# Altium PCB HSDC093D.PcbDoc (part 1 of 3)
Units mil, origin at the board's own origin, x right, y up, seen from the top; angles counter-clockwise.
Board outline 4360 x 2202.42 mil, 6 copper layers (Top Layer, GND1, VCC1, VCC2, GND2, Bottom Layer), stack 84.434 mil thick; 280 components, 182 nets, 800 pads, 401 vias.
Unrouted connection lines stored in the file: 5.
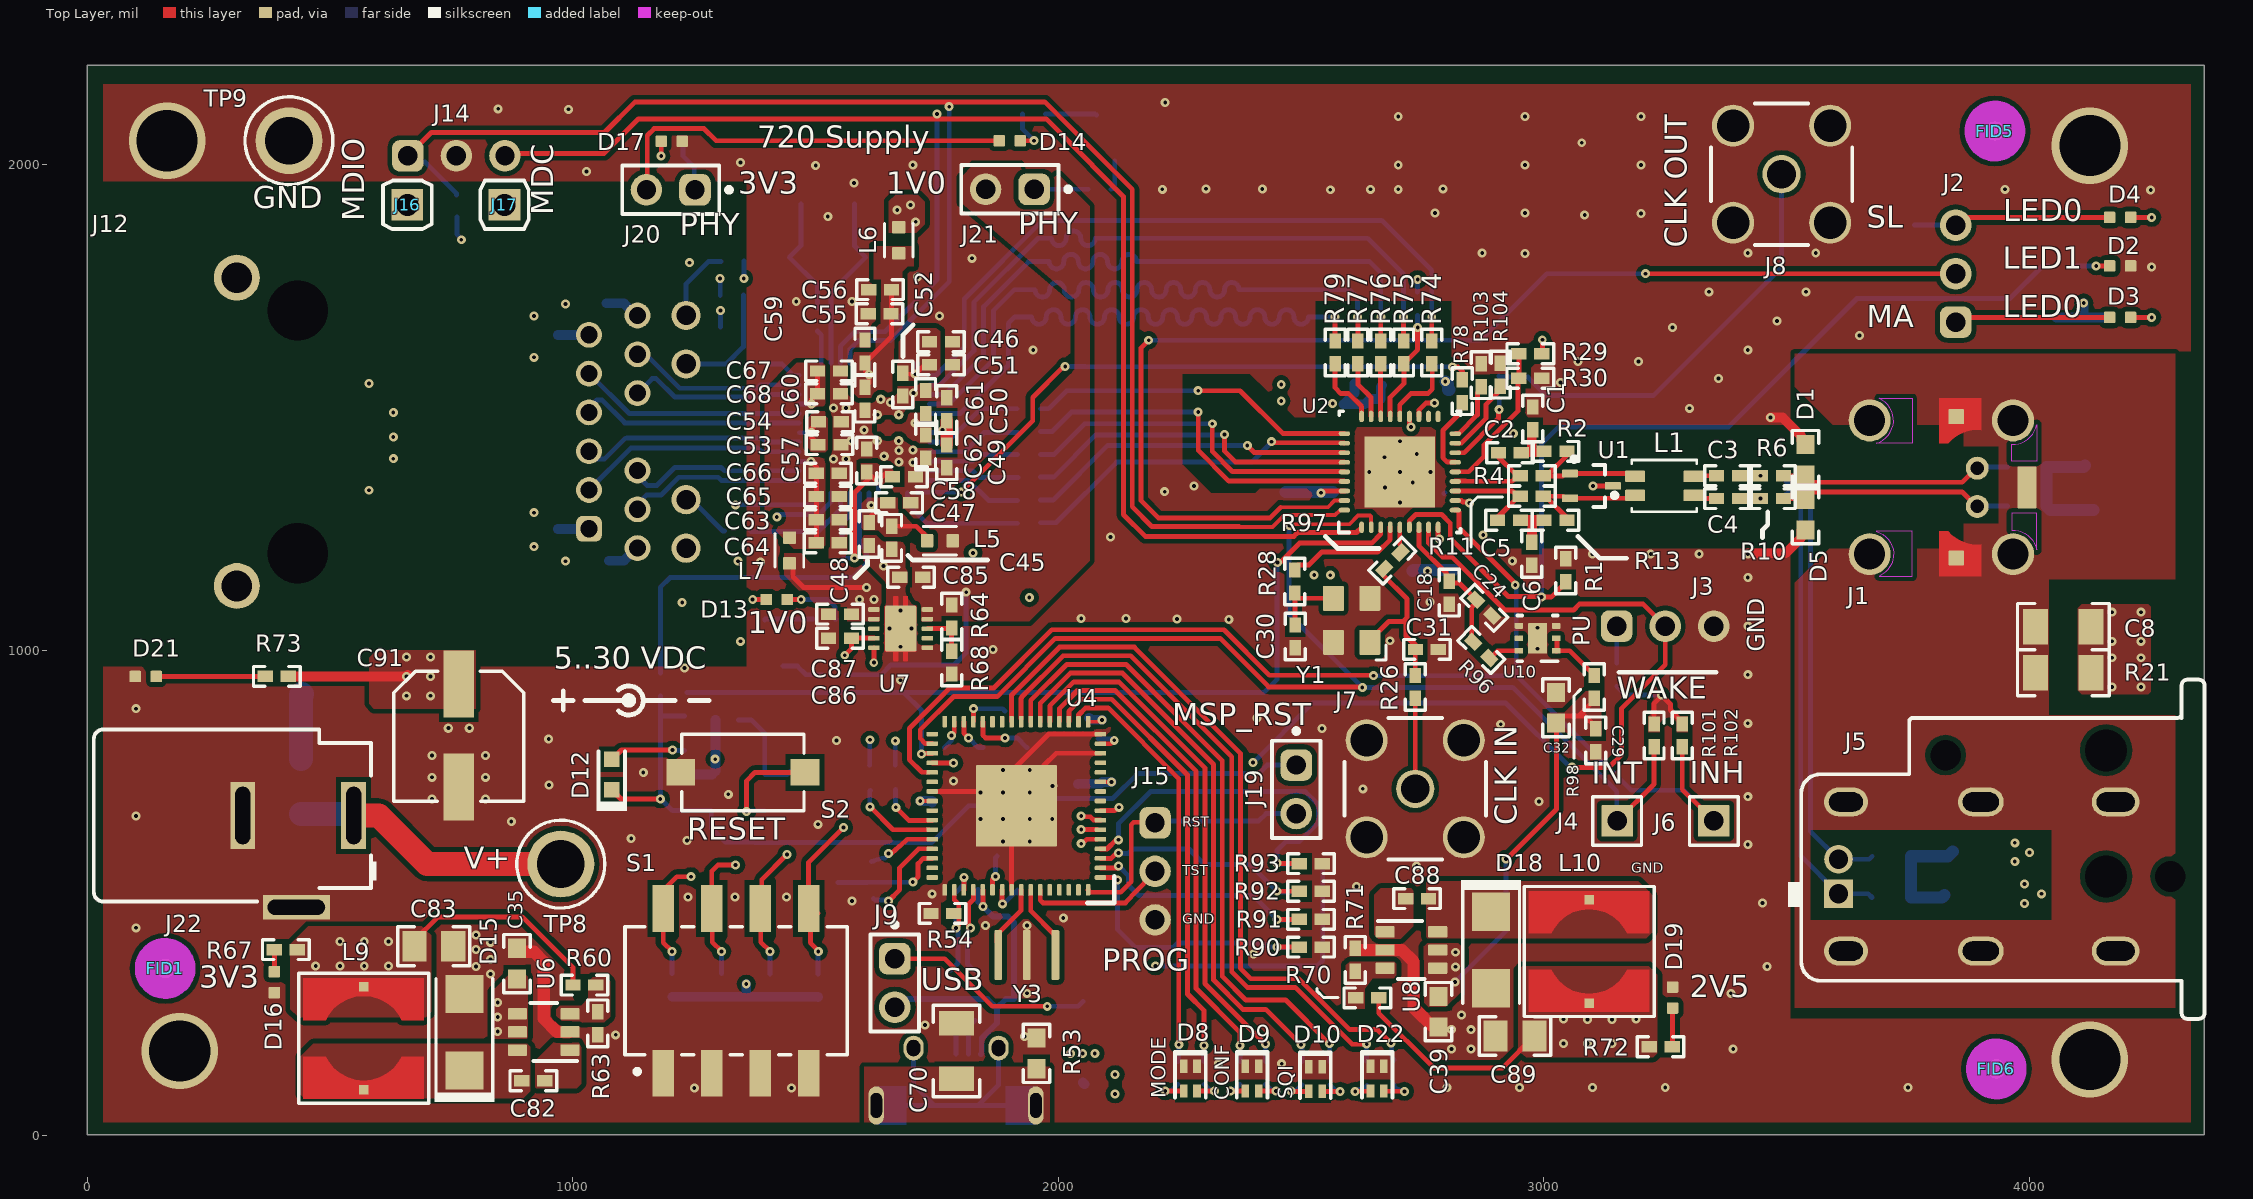
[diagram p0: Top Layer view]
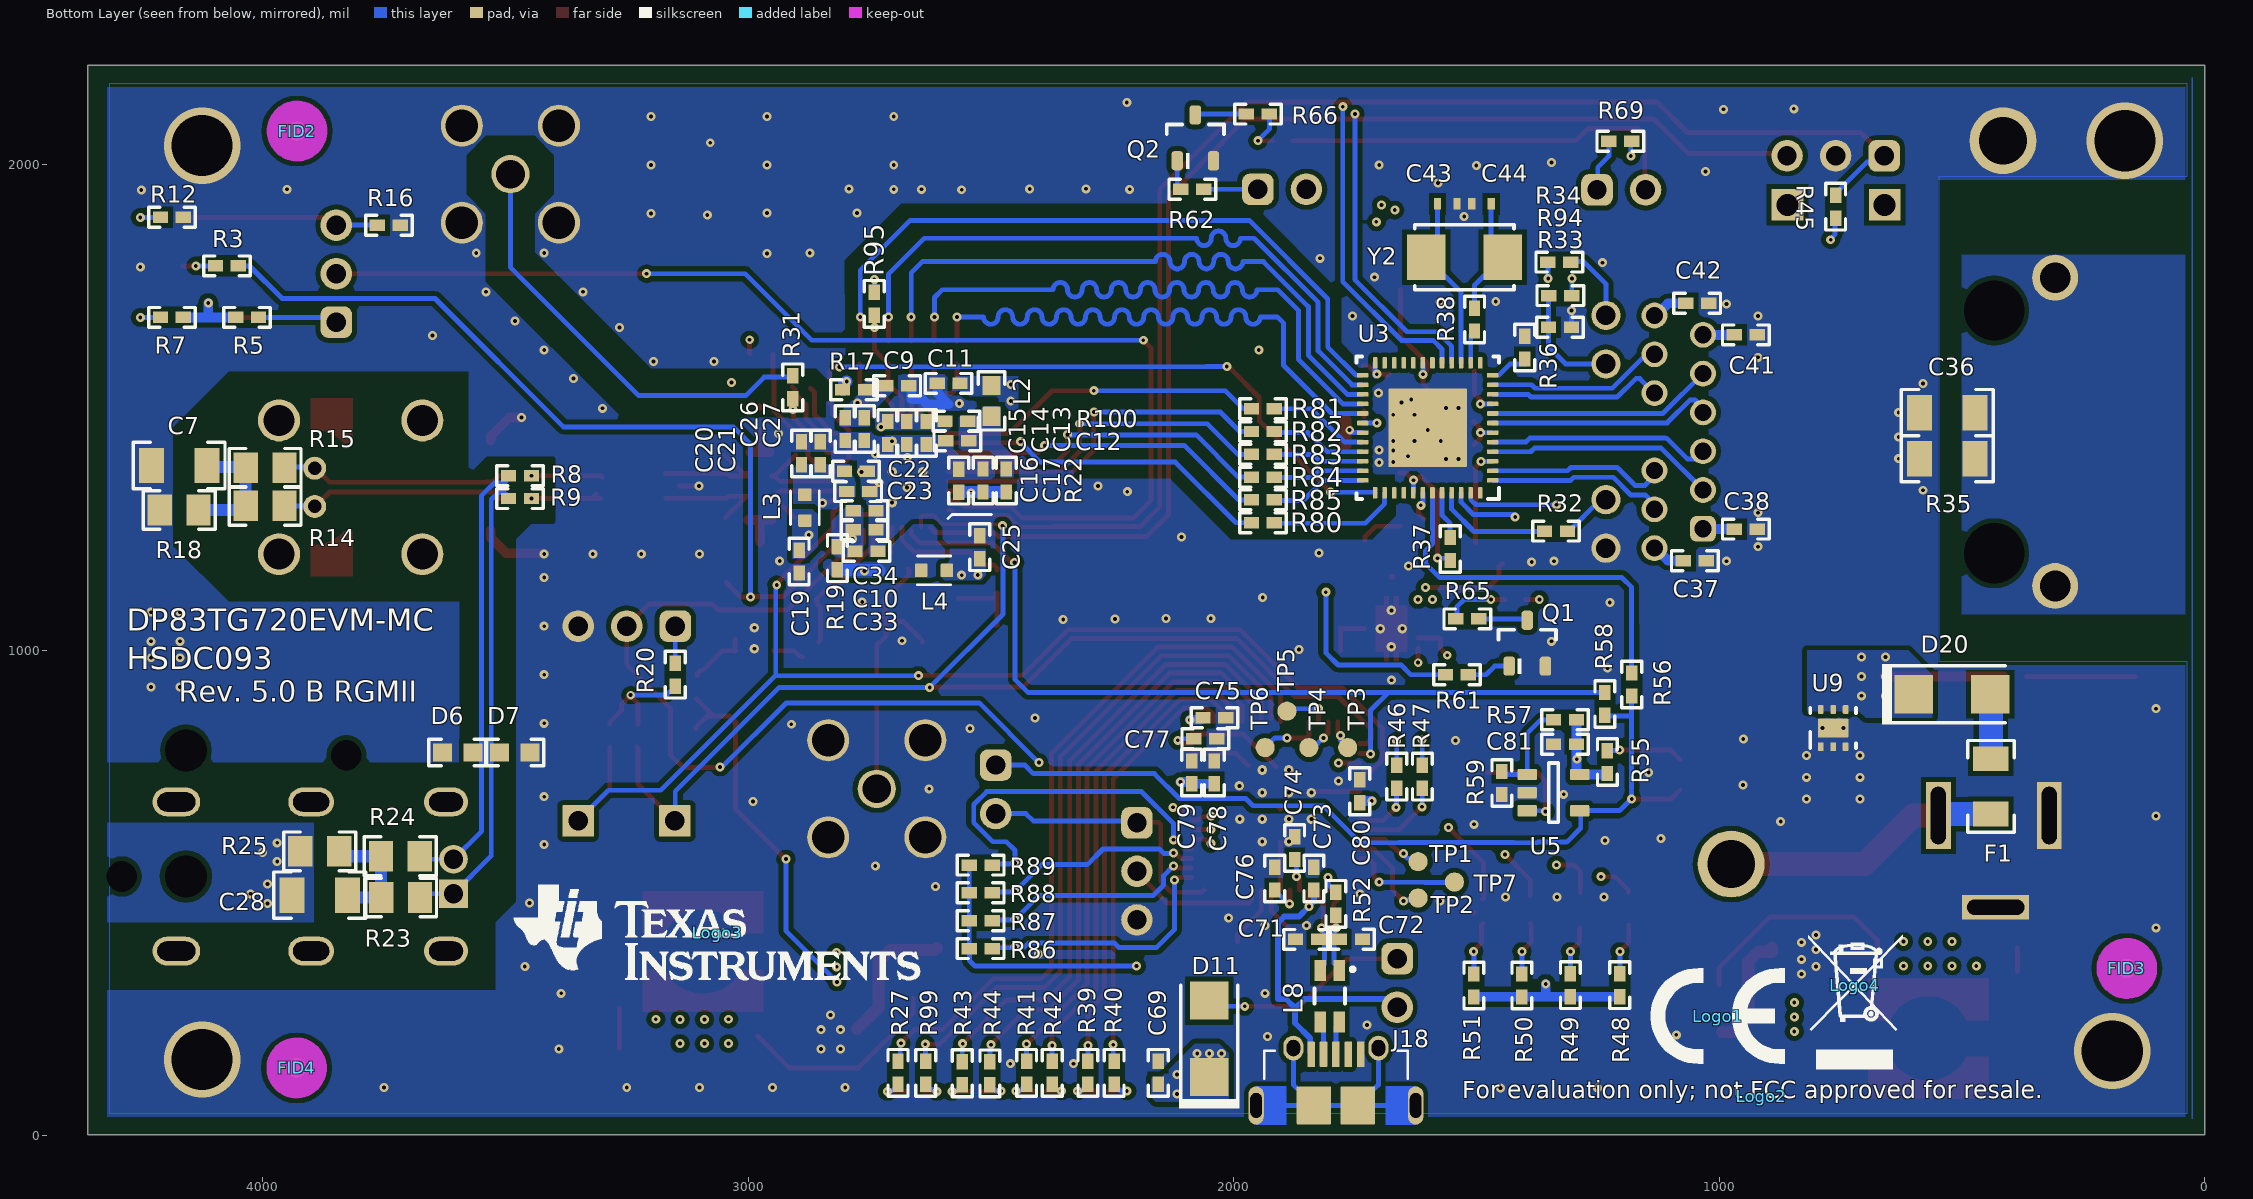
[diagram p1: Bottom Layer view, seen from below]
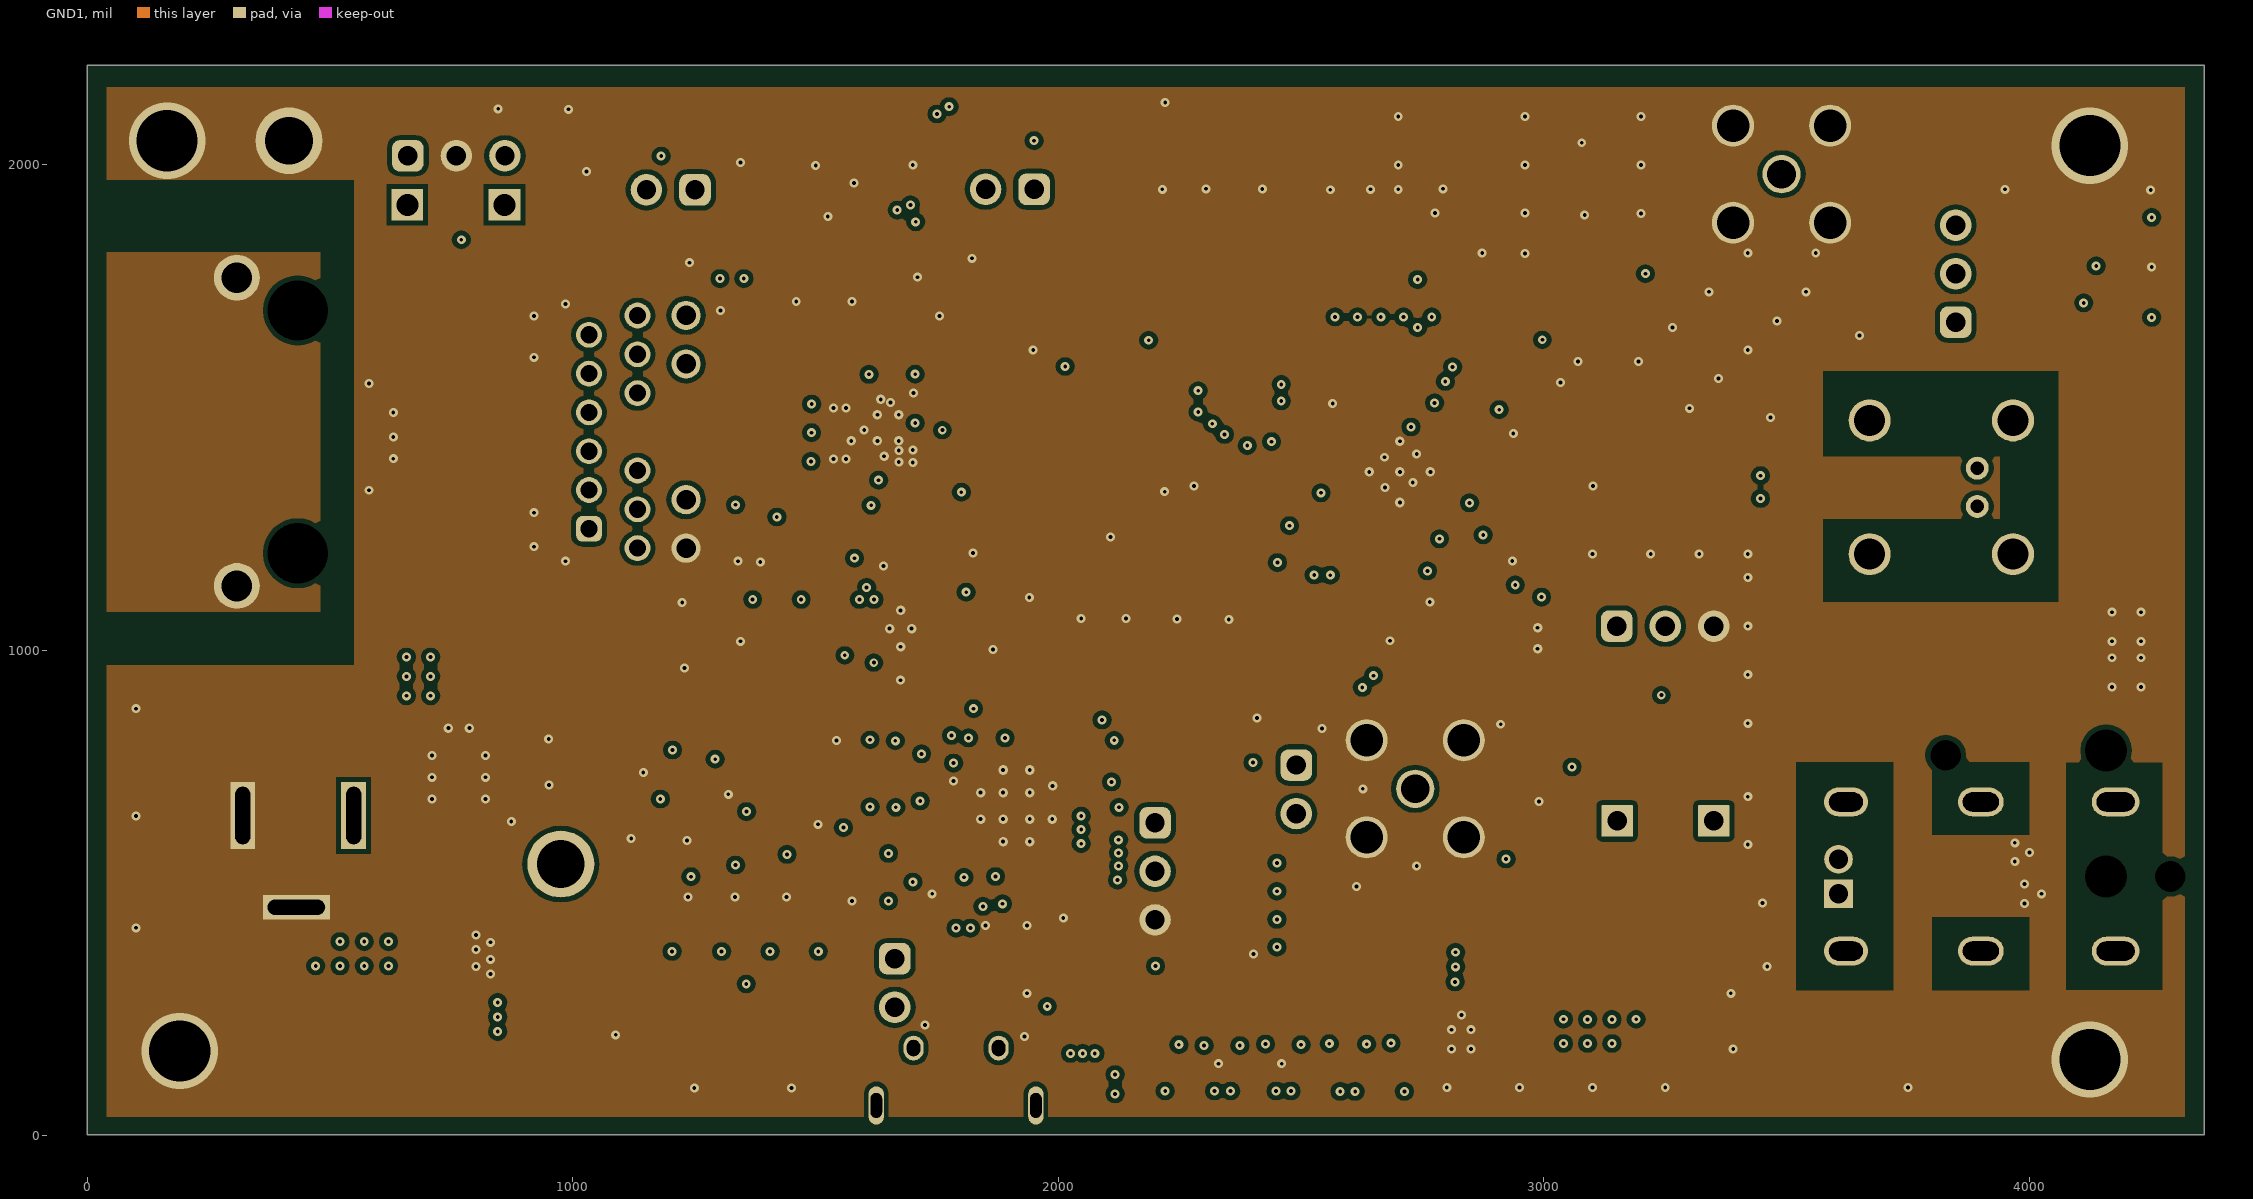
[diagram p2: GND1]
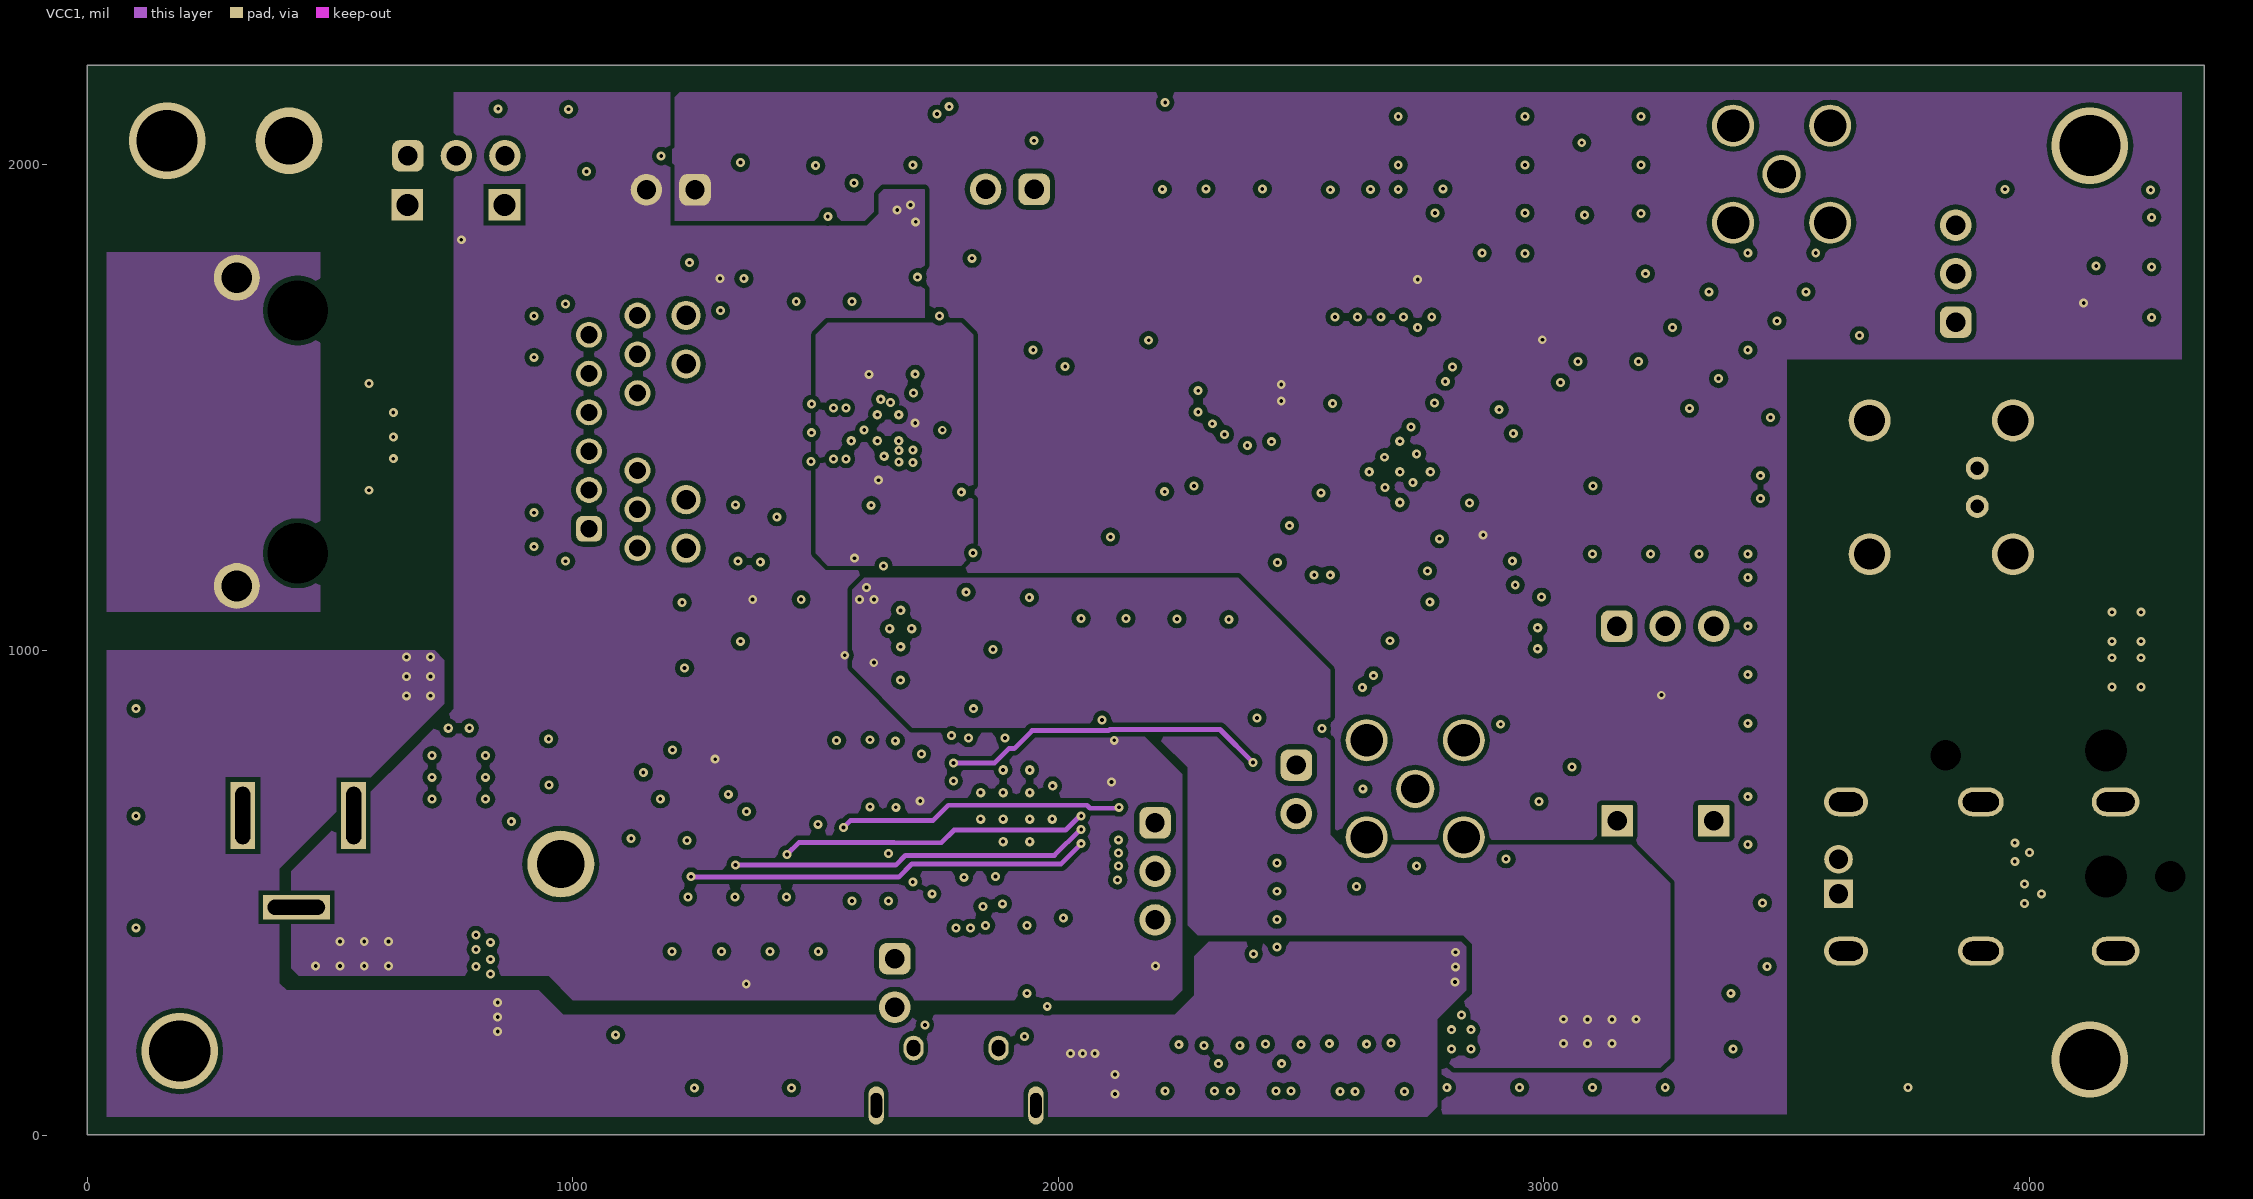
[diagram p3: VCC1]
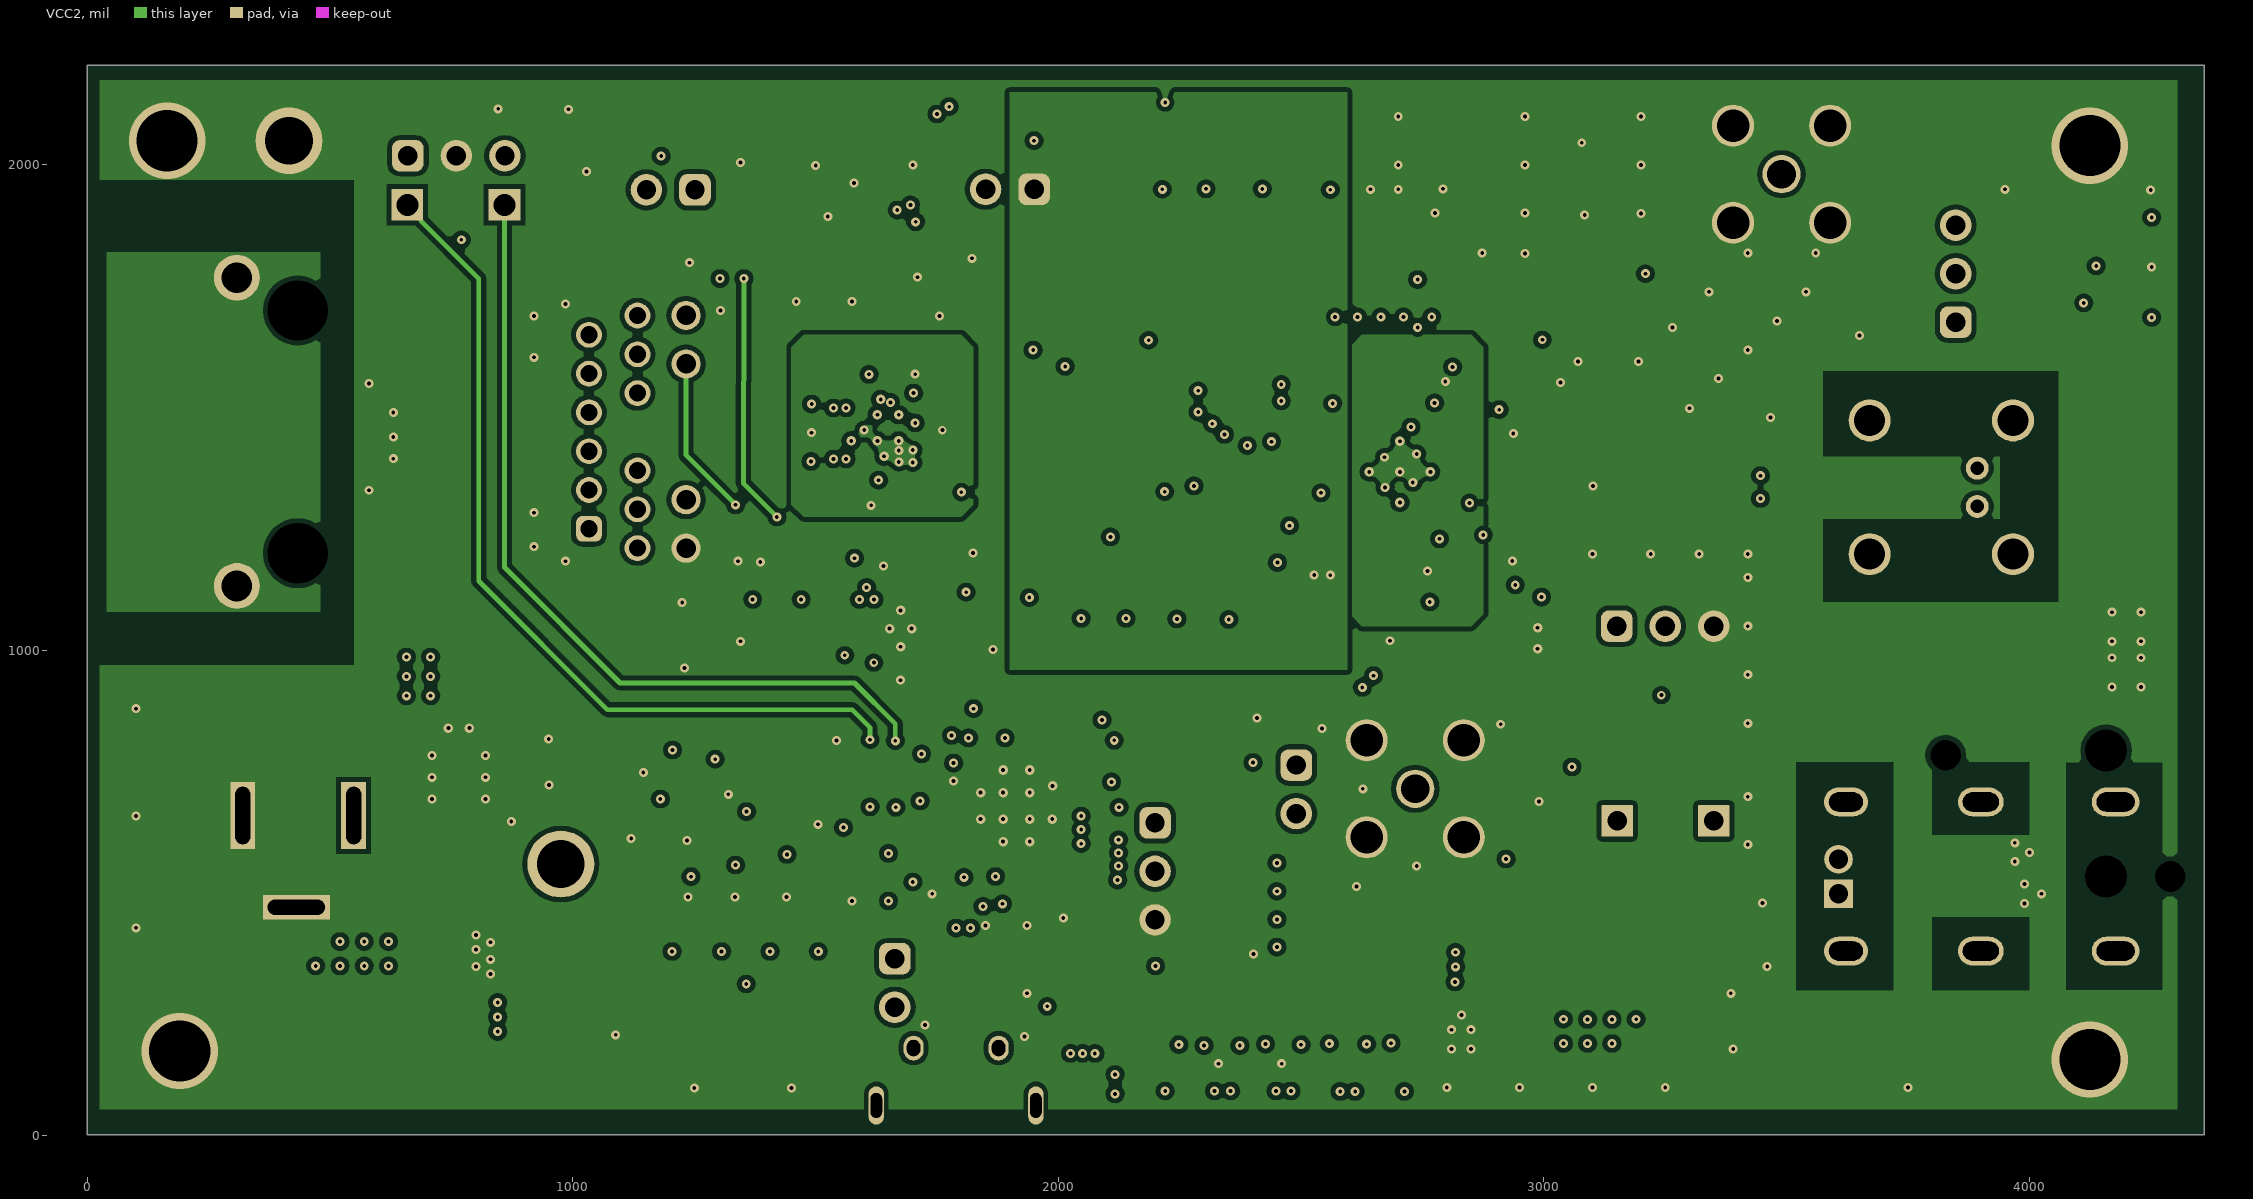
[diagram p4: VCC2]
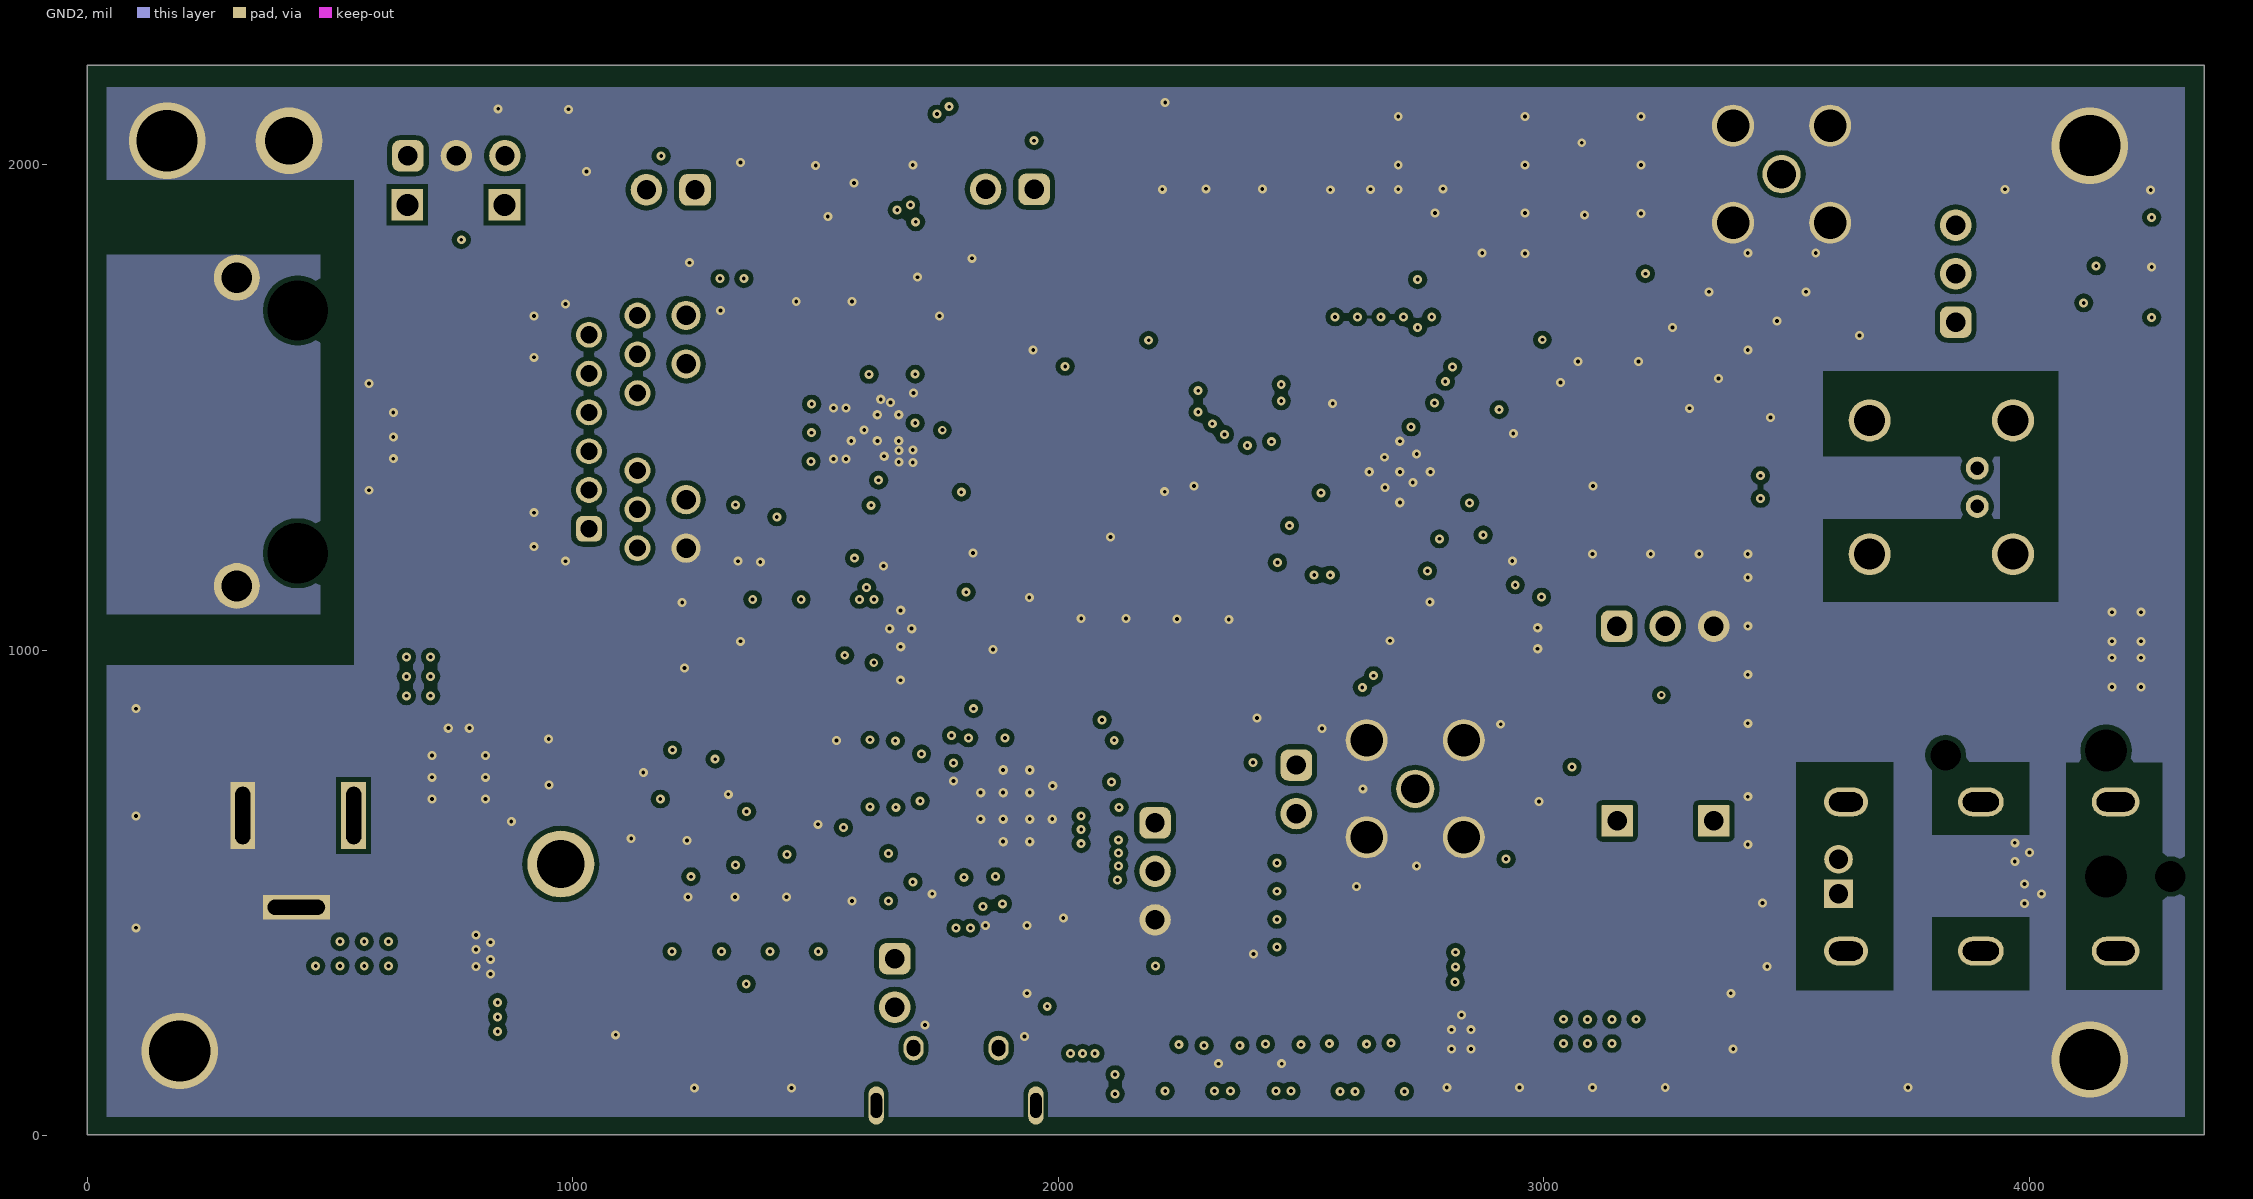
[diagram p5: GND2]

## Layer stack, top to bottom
Top Solder: solder mask 0.4, Solder Resist, Dk 3.5
Top Layer: signal copper 1.4
Dielectric 1: prepreg 8, FR-4, Dk 4.2
GND1: signal copper 1.417
Dielectric 2: dielectric 10, Dk 4.2
VCC1: signal copper 1.4
Dielectric 3: core 40, FR-4, Dk 4.2
VCC2: signal copper 1.4
Dielectric 4: prepreg 8, FR-4, Dk 4.2
GND2: signal copper 1.417
Dielectric 5: dielectric 10, Dk 4.2
Bottom Layer: signal copper 1.4
Bottom Solder: solder mask 0.4, Solder Resist, Dk 3.5

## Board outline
0,2.58 4360,2.58 4360,2205 0,2205

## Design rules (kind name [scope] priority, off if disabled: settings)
AcuteAngle [All] p1: minimum=4.50000000000000E+0001 checktracksonly=FALSE
AssemblyTestPointUsage [All] p1: valid=2
BoardOutlineClearance BoardOutlineClearance_MountingHoles [OnCopper and InComponentClass('Mounting Holes')] p1: gap=39.37 ignorepadtopadclearanceinfootprint=FALSE
BoardOutlineClearance BoardOutlineClearance_Poly [OnCopper and IsPoly] p2: gap=25 ignorepadtopadclearanceinfootprint=FALSE
BoardOutlineClearance [OnCopper and Not InComponentClass('Logo') and not InComponentClass('FiducialMark') and not InRegion(1000,500,4000,800) and not InPoly] p3: gap=75 ignorepadtopadclearanceinfootprint=FALSE
Clearance Logo [InNet('No Net') And OnLayer('Top Overlay') vs (ObjectKind = 'Component') And ((Name = 'Logo3'))] p1: gap=0 ignorepadtopadclearanceinfootprint=TRUE
Clearance Clearance_Keepouts [((IsTrack Or IsArc) And Not InPoly) And IsFree and IsKeepOut vs ((IsTrack Or IsArc) And Not InPoly) And IsFree and IsKeepOut] p2: gap=0 ignorepadtopadclearanceinfootprint=FALSE
Clearance Clearance_Poly [InPolygon] p3: gap=9.84 ignorepadtopadclearanceinfootprint=TRUE
Clearance Clearance_FiducialMark [IsKeepOut and InComponentClass('FiducialMark') vs IsPad and InComponentClass('FiducialMark')] p4: gap=0 ignorepadtopadclearanceinfootprint=FALSE
Clearance [All vs (ObjectKind = 'Component') And ((Name = 'C31') or (Name = 'C35'))] p5: gap=0 ignorepadtopadclearanceinfootprint=TRUE
Clearance Clearance_1 [All] p6: gap=7.87 ignorepadtopadclearanceinfootprint=TRUE
ComponentClearance ComponentClearance_MountingHoles_FiducialMarks [InComponentClass('Mounting Holes') vs InComponentClass('FiducialMark')] p1: gap=50 collisioncheckmode=3 verticalgap=10 showdistances=FALSE
ComponentClearance ComponentClearance_Shunt [InComponentClass('Header') vs InComponentClass('Shunt')] p2: gap=0 collisioncheckmode=3 verticalgap=0 showdistances=FALSE
ComponentClearance ComponentClearance_Logo [InComponentClass('Logo')] p3: gap=50 collisioncheckmode=3 verticalgap=10 showdistances=FALSE
ComponentClearance ComponentClearance_ScrewToNut [(HasFootprint('NY PMS 440 0025 PH')) vs (HasFootprint('Keystone_1902C'))] p4: gap=5 collisioncheckmode=3 verticalgap=10 showdistances=FALSE
ComponentClearance ComponentClearance_MountingHoles [InComponentClass('Mounting Holes')] p5: gap=250 collisioncheckmode=3 verticalgap=100000 showdistances=FALSE
ComponentClearance ComponentClearance_SmallPassives [HasFootprint('0201*') or HasFootprint('0402*') or HasFootprint('0508') or HasFootprint('0603*') or HasFootprint('0612') or HasFootprint('0805*') or HasFootprint('0815*') or HasFootprint('0830*') or HasFootprint('1206*') or HasFootprint('1210*') or HasFootprint('1808*') or HasFootprint('1812*') or HasFootprint('1825*') or HasFootprint('2010*') or HasFootprint('2220*') or HasFootprint('2225*') or HasFootprint('2512*') or HasFootprint('2728*') or HasFootprint('3518*') vs HasFootprint('0201*') or HasFootprint('0402*') or HasFootprint('0508') or HasFootprint('0603*') or HasFootprint('0612') or HasFootprint('0805*') or HasFootprint('0815*') or HasFootprint('0830*') or HasFootprint('1206*') or HasFootprint('1210*') or HasFootprint('1808*') or HasFootprint('1812*') or HasFootprint('1825*') or HasFootprint('2010*') or HasFootprint('2220*') or HasFootprint('2225*') or HasFootprint('2512*') or HasFootprint('2728*') or HasFootprint('3518*')] p6: gap=14.96 collisioncheckmode=3 verticalgap=10 showdistances=FALSE
ComponentClearance ComponentClearance_THtoSMT [IsThruComponent vs IsSMTComponent] p7: gap=40 collisioncheckmode=3 verticalgap=30 showdistances=FALSE
ComponentClearance ComponentClearance_THtoTH [IsThruComponent vs IsThruComponent] p8: gap=30 collisioncheckmode=3 verticalgap=30 showdistances=FALSE
ComponentClearance [All] p9: gap=30 collisioncheckmode=3 verticalgap=10 showdistances=FALSE
DiffPairsRouting [All] p1: maxlimit=100 minlimit=10 mostfreqgap=10 toplayer_maxgap=10 toplayer_minwidth=10 toplayer_maxwidth=10 toplayer_prefwidth=10 midlayer1_maxgap=10 midlayer1_minwidth=10 midlayer1_maxwidth=10 midlayer1_prefwidth=10 midlayer2_maxgap=10 midlayer2_minwidth=10 midlayer2_maxwidth=10 midlayer2_prefwidth=10 midlayer3_minwidth=15 midlayer3_maxwidth=15 midlayer3_prefwidth=15 midlayer4_minwidth=15 midlayer4_maxwidth=15 midlayer4_prefwidth=15 bottomlayer_maxgap=10 bottomlayer_minwidth=10 bottomlayer_maxwidth=10 bottomlayer_prefwidth=10 maxuncoupledlength=1000
FabricationTestPointUsage TestPointUsage [All] p1: valid=2 allowmultiple=FALSE
FabricationTestpoint Testpoint [All] p1: side=3 testpointundercomponent=TRUE minsize=40 maxsize=100 preferedsize=60 minholesize=0 maxholesize=40 preferedholesize=32 testpointgrid=1 allowsidetop=TRUE allowsidebottom=TRUE usegrid=TRUE gridtolerance=0.01
FanoutControl Fanout_LCC [IsLCC] p1: bgadir=Out bgaviamode=Centered fanoutstyle=Auto fanoutdirection=Alternating viagrid=1 // Fanout_LCC (Default Rule)
FanoutControl Fanout_BGA [IsBGA] p2: bgadir=Out bgaviamode=Centered fanoutstyle=Auto fanoutdirection=Alternating viagrid=1 // Fanout_BGA (Default Rule)
FanoutControl Fanout_Default [All] p4: bgadir=Out bgaviamode=Centered fanoutstyle=Auto fanoutdirection=Alternating viagrid=1 // Fanout_Default (Default Rule)
FanoutControl Fanout_Small [(CompPinCount < 5)] p5: bgadir=Out bgaviamode=Centered fanoutstyle=Auto fanoutdirection=OutThenIn viagrid=1 // Fanout_Small (Default Rule)
HoleSize [All] p1: absolutevalues=TRUE maxlimit=251 minlimit=7.87 maxpercent=80.000 minpercent=20.000
MinimumAnnularRing MinimumAnnularRing_ThermalPadVias [IsVia and InAnyComponent] p1: minimumring=4.92
MinimumAnnularRing [All] p2: minimumring=4.92
MinimumSolderMaskSliver MinimumSolderMaskSliver_Logo [InComponentClass('Logo') vs InComponentClass('Logo')] p1: minsoldermaskwidth=0.7
MinimumSolderMaskSliver [All] p2: minsoldermaskwidth=3.94
PlaneConnect [All] p1: planeconnectstyle=Direct reliefexpansion=10 reliefentries=4 reliefconductorwidth=10 reliefairgap=10
PolygonConnect [All] p1: connectstyle=Direct reliefconductorwidth=10 reliefentries=4 polygonreliefangle="90 Angle" airgapwidth=10
RoutingVias ThermalPadVias [IsVia and InAnyComponent] p1: holewidth=7.87 width=17.72 viastyle="Through Hole" minholewidth=7.87 minwidth=17.72 maxholewidth=12.99 maxwidth=23.62
RoutingVias [All] p2: holewidth=7.87 width=17.72 viastyle="Through Hole" minholewidth=7.87 minwidth=17.72 maxholewidth=40 maxwidth=65
SilkToBoardRegionClearance [Not ((IsComment or IsDesignator) And (Hide <> 'False')) and not InRegion(1000,500,4000,800)] p1:
SilkToSilkClearance TI_Logo [All vs Logo3] p1: silktosilkclearance=0
SilkToSilkClearance SilkToSilkClearance_Pb-FreeLogo [(HasFootprint('Pb-Free_Overlay_Medium') OR HasFootprint('Pb-Free_Overlay_Small')) vs (HasFootprint('Pb-Free_Overlay_Medium') OR HasFootprint('Pb-Free_Overlay_Small'))] p2: silktosilkclearance=0
SilkToSilkClearance [All] p3: silktosilkclearance=3.94
SilkToSolderMaskClearance SilkToComponentPadClearance [(IsPad or IsFill or IsRegion) and InAnycomponent] p1: minsilkscreentomaskgap=5 clearancetoexposedcopper=TRUE
SilkToSolderMaskClearance "Silk to Solder Mask Opening" [All] p2: minsilkscreentomaskgap=3.94 clearancetoexposedcopper=FALSE
SolderMaskExpansion [All] p1: expansion=1.97 istentingtop=FALSE
UnRoutedNet [All] p1: checkbadconnections=TRUE
Width [All] p1: maxlimit=100 minlimit=6 preferedwidth=10 checkconnectedcopper=TRUE
14 further rules are at their usual default settings.

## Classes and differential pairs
component class HSDC093B_Hardware: FID1 FID2 FID3 FID4 FID5 FID6 Logo1 Logo2 Logo3 Logo4
component class Logo: Logo3
component class HSDC093B_720: 22 C1 C2 C3 C4 C5 C6 C7 C8 C9 C10 C11 C12 C13 C14 C15 C16 C17 C18 C19 C20 C21 C22 C23 C24 C25 C26 C27 C28 C29 C30 C31 C32 C33 C34 D1 D2 D3 D4 D5 D6 D7 J1 J2 J3 J4 J5 J6 J7 J8 L1 L2 L3 L4 R1 R2 R3 R4 R5 R6 R7 R8 R9 R10 R11 R12 R13 R14 R15 R16 R17 R18 R19 R20 R21 R22 R23 R24 R25 R26 R28 R29 R30 R31 R74 R75 R76 R77 R78 R79 R95 R96 R97 R98 R100 R101 R102 R103 R104 U1 U2 U10 Y1
component class HSDC093B_867: C36 C37 C38 C41 C42 C43 C44 C45 C46 C47 C48 C49 C50 C51 C52 C53 C54 C55 C56 C57 C58 C59 C60 C61 C62 C63 C64 C65 C66 C67 C68 J12 L5 L6 L7 R32 R33 R34 R35 R36 R37 R38 R80 R81 R82 R83 R84 R85 R94 U3 Y2
component class HSDC093B_Controller: C69 C70 C71 C72 C73 C74 C75 C76 C77 C78 C79 C80 C81 D8 D9 D10 D11 D12 D22 J9 J14 J15 J16 J17 J18 J19 L8 R27 R39 R40 R41 R42 R43 R44 R45 R46 R47 R48 R49 R50 R51 R52 R53 R54 R55 R56 R57 R58 R59 R86 R87 R88 R89 R90 R91 R92 R93 R99 S1 S2 TP1 TP2 TP3 TP4 TP5 TP6 TP7 U4 U5 Y3
component class Header: J2 J3 J4 J6 J9 J14 J15 J16 J17 J19 J20 J21
component class HSDC093B_Power_Sup: C35 C39 C82 C83 C85 C86 C87 C88 C89 C91 D13 D14 D15 D16 D17 D18 D19 D20 D21 F1 J20 J21 J22 L9 L10 Q1 Q2 R60 R61 R62 R63 R64 R65 R66 R67 R68 R69 R70 R71 R72 R73 TP8 TP9 U6 U7 U8 U9
component class FiducialMark: FID1 FID2 FID3 FID4 FID5 FID6
differential pair TRD2: +TRD2_P -TRD2_N
differential pair TRD1: +TRD1_P -TRD1_N
differential pair TRD: +TRD_P -TRD_N
differential pair USB1_D: +USB1_D_P -USB1_D_N
differential pair USB_D: +USB_D_P -USB_D_N
differential pair TD_A: +TD_A_P -TD_A_N
differential pair TD_B: +TD_B_P -TD_B_N
differential pair TD_C: +TD_C_P -TD_C_N
differential pair TD_D: +TD_D_P -TD_D_N
differential pair CON1: +CON1_P -CON1_N
differential pair CON2: +CON2_P -CON2_N

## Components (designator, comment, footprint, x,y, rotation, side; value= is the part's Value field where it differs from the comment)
C1 "GRM1555C1H470FA01D" 0402 2977,1478 r270 top value=47pF
C2 "GRM1555C1H220FA01D" 0402 2930,1407 r180 top value=22pF
C3 "0402YC104KAT2A" 0402 3379.38,1360 r180 top value=0.1uF
C4 "0402YC104KAT2A" 0402 3379.38,1313 r180 top value=0.1uF
C5 "GRM1555C1H220FA01D" 0402 2928,1268 r0 top value=22pF
C6 "GRM1555C1H470FA01D" 0402 2975,1199 r270 top value=47pF
C7 "GRM31BR73A472KW01L" 1206 4171.95,1381.11 r0 bottom value=4700pF
C8 "C1206X103KDRAC7800" 1206 4070,1049 r180 top value=0.01uF
C9 "C1005X5R1H104K050BB" 0402 2693,1545 r180 bottom value=0.1uF
C10 "C1005X5R1H104K050BB" 0402 2760,1249 r180 bottom value=0.1uF
C11 "GRM155R61A106ME11" 0402 2587,1550 r0 bottom value=10uF
C12 "GRM155R61A106ME11" 0402 2569,1432 r0 bottom value=10uF
C13 "C1005X5R1A225K050BC" 0402 2633,1448 r270 bottom value=2.2uF
C14 "C1005X5R1H104K050BB" 0402 2673,1448 r270 bottom value=0.1uF
C15 "GRM155R61A103KA01D" 0402 2712,1448 r270 bottom value=0.01uF
C16 "C1005X5R1H104K050BB" 0402 2566.14,1349.72 r90 bottom value=0.1uF
C17 "GRM155R61A103KA01D" 0402 2516.14,1350.03 r90 bottom value=0.01uF
C18 "C1005X5R1H104K050BB" 0402 2805,1119 r270 top value=0.1uF
C19 "GRM155R61A106ME11" 0402 2895,1183 r270 bottom value=10uF
C20 "GRM155R61A106ME11" 0402 2890,1406 r90 bottom value=10uF
C21 "C1005X5R1A225K050BC" 0402 2851,1406 r90 bottom value=2.2uF
C22 "C1005X5R1H104K050BB" 0402 2778,1369 r180 bottom value=0.1uF
C23 "GRM155R61A103KA01D" 0402 2773.14,1327.41 r180 bottom value=0.01uF
C24 "GRM155R61A106ME11" 0402 2877,1088 r315 top value=10uF
C25 "GRM155R61A106ME11" 0402 2523,1212.62 r90 bottom value=10uF
C26 "C1005X5R1A225K050BC" 0402 2800,1456 r270 bottom value=2.2uF
C27 "GRM155R61A103KA01D" 0402 2761,1456 r270 bottom value=0.01uF
C28 "GRM31BR73A472KW01L" 1206 3882.28,496.09 r0 bottom value=4700pF
C29 "C1005X5R1H104K050BB" 0402 3107,815 r270 top value=0.1uF
C30 "GRM1555C1H220FA01D" 0402 2488,1029 r270 top value=22pF
C31 "GRM1555C1H220FA01D" 0402 2759,1002 r0 top value=22pF
C32 "C1608X5R1E106M080AC" 0603 3025,882 r90 top value=10uF
C33 "GRM155R61A103KA01D" 0402 2756,1204 r180 bottom value=0.01uF
C34 "C1005X5R1A225K050BC" 0402 2760,1288 r180 bottom value=2.2uF
C35 "C1608X5R1V225K080AC" 0603 885,355 r90 top value=2.2uF
C36 "C1206X103KDRAC7800" 1206 530,1490 r180 bottom value=0.01uF
C37 "C1005X5R1H104K050BB" 0402 1050,1185 r0 bottom value=0.1uF
C38 "C1005X5R1H104K050BB" 0402 945,1250 r0 bottom value=0.1uF
C39 "C1608X5R1V225K080AC" 0603 2783,256 r270 top value=2.2uF
C41 "C1005X5R1H104K050BB" 0402 945,1650 r0 bottom value=0.1uF
C42 "C1005X5R1H104K050BB" 0402 1045,1715 r0 bottom value=0.1uF
C43 "GRM1555C1E270JA01D" 0402S 1560,1919.81 r180 bottom value=27pF
C44 "GRM1555C1E270JA01D" 0402S 1489.53,1919.81 r180 bottom value=27pF
C45 "GRM155R61A106ME11" 0402 1656.38,1232.13 r270 top value=10uF
C46 "GRM155R61E105KA12D" 0402 1758.19,1635.86 r0 top value=1uF
C47 "C1005X5R1H104K050BB" 0402 1672,1304 r0 top value=0.1uF
C48 "GRM155R61A103KA01D" 0402 1610,1240 r270 top value=0.01uF
C49 "C1005X5R1H104K050BB" 0402 1770,1399.77 r270 top value=0.1uF
C50 "GRM155R61A103KA01D" 0402 1770,1497.03 r90 top value=0.01uF
C51 "C1005X5R1H104K050BB" 0402 1758.19,1588.37 r0 top value=0.1uF
C52 "GRM155R61A103KA01D" 0402 1679.42,1547.62 r270 top value=0.01uF
C53 "C1005X5R1H104K050BB" 0402 1528.58,1424.13 r0 top value=0.1uF
C54 "GRM155R61A103KA01D" 0402 1529.29,1471.38 r0 top value=0.01uF
C55 "GRM155R61A106ME11" 0402 1631.73,1693.39 r180 top value=10uF
C56 "GRM155R61E105KA12D" 0402 1632.76,1743.39 r180 top value=1uF
C57 "C1005X5R1H104K050BB" 0402 1605,1391.34 r90 top value=0.1uF
C58 "GRM155R61A103KA01D" 0402 1681.97,1357.7 r0 top value=0.01uF
C59 "C1005X5R1H104K050BB" 0402 1601.58,1615.91 r90 top value=0.1uF
C60 "GRM155R61A103KA01D" 0402 1601.58,1518.62 r270 top value=0.01uF
C61 "C1005X5R1H104K050BB" 0402 1726.38,1511.77 r90 top value=0.1uF
C62 "GRM155R61A103KA01D" 0402 1726.38,1420 r270 top value=0.01uF
C63 "GRM155R61A106ME11" 0402 1525,1269.37 r0 top value=10uF
C64 "GRM155R61E105KA12D" 0402 1525,1221.54 r0 top value=1uF
C65 "C1005X5R1H104K050BB" 0402 1525,1317.14 r0 top value=0.1uF
C66 "GRM155R61A103KA01D" 0402 1525,1365.24 r0 top value=0.01uF
C67 "C1005X5R1H104K050BB" 0402 1527.37,1575.67 r0 top value=0.1uF
C68 "GRM155R61A103KA01D" 0402 1527.37,1528.62 r0 top value=0.01uF
C69 "C1005X5R1H104K050BB" 0402 2155,129.98 r90 bottom value=0.1uF
C70 "C1206X103KDRAC7800" 1206 1790,175 r270 top value=0.01uF
C71 "GRM1555C1H100FA01D" 0402 1848.69,404.74 r180 bottom value=10pF
C72 "GRM1555C1H100FA01D" 0402 1758.19,405 r0 bottom value=10pF
C73 "C1005X5R1A475K050BC" 0402_065 1834.48,530 r90 bottom value=4.7uF
C74 "GRM155R61A224KE19D" 0402 1874.43,592.94 r270 bottom value=0.22uF
C75 "04026D474KAT2A" 0402 2039.53,861.3 r0 bottom value=0.47uF
C76 "GRM155R61A224KE19D" 0402 1915.19,530 r90 bottom value=0.22uF
C77 "C1005X5R1H104K050BB" 0402 2058.19,817.99 r180 bottom value=0.1uF
C78 "GRM155R61A106ME11" 0402 2039.53,748.9 r90 bottom value=10uF
C79 "C1005X5R1H104K050BB" 0402 2086.65,748.9 r90 bottom value=0.1uF
C80 "C1005X5R1H104K050BB" 0402 1740,710 r90 bottom value=0.1uF
C81 "C1005X5R1H104K050BB" 0402 1317.3,807.09 r0 bottom value=0.1uF
C82 "C1005X5R1H104K050BB" 0402 918.38,113.88 r180 top value=0.1uF
C83 "C2012X5R1A476M125AC" 0805_HV 713.48,390.61 r0 top value=47uF
C85 "GRM155R61A106ME11" 0402 1696.64,1150.52 r180 top value=10uF
C86 "GRM155R61E105KA12D" 0402 1550,1025 r180 top value=1uF
C87 "GRM155R61E105KA12D" 0402 1550,1075 r180 top value=1uF
C88 "C1005X5R1H104K050BB" 0402 2738.88,488.89 r0 top value=0.1uF
C89 "C2012X5R1A476M125AC" 0805_HV 2940.48,205.89 r180 top value=47uF
C91 "EMVA350ADA101MF80G" CAPSMT_62_F80 765,825 r270 top value=100uF
D1 "EZAEG3W11AV" 0603 3539,1393 r90 top
D2 "150040GS73240" WL-SMCC_0402_Green 4186.87,1792.09 r180 top value=Green
D3 "150040GS73240" WL-SMCC_0402_Green 4186.87,1686 r0 top value=Green
D4 "150040GS73240" WL-SMCC_0402_Green 4186.87,1892.09 r180 top value=Green
D5 "EZAEG3W11AV" 0603 3539,1280 r90 top
D6 "EZAEG3W11AV" 0603 3598,790 r180 bottom
D7 "EZAEG3W11AV" 0603 3481,790 r0 bottom
D8 "HSMF-C165" HSMF-C165_RG 2271.81,118.15 r90 top value=Rg
D9 "HSMF-C165" HSMF-C165_RG 2398.97,118.15 r90 top value=Rg
D10 "HSMF-C165" HSMF-C165_RG 2529.37,117.27 r90 top value=Rg
D11 "NRVBA160T3G" SMA 2050,200 r90 bottom value=60V
D12 "150060RS75000" WL-SMCW_RED 1080,744.49 r90 top value=Red
D13 "150040GS73240" WL-SMCC_0402_Green 1420,1105 r180 top value=Green
D14 "150040GS73240" WL-SMCC_0402_Green 1900,2050 r180 top value=Green
D15 "B160-13-F" SMA 776.41,213.44 r90 top value=60V
D16 "150040GS73240" WL-SMCC_0402_Green 385,316.79 r90 top value=Green
D17 "150040GS73240" WL-SMCC_0402_Green 1203.42,2048.82 r180 top value=Green
D18 "B160-13-F" SMA 2891.27,382.95 r270 top value=60V
D19 "150040GS73240" WL-SMCC_0402_Green 3265,285 r270 top value=Green
D20 "NRVBA160T3G" SMA 520,910 r180 bottom value=60V
D21 "150040GS73240" WL-SMCC_0402_Green 120,946.46 r0 top value=Green
D22 "HSMF-C165" HSMF-C165_RG 2656.53,118.15 r90 top value=Rg
F1 "0440.500WR" 1206 440,720 r270 bottom
FID1 "Fiducial" Fiducial10-30 160,345 r0 top
FID2 "Fiducial" Fiducial10-30 3929,2070 r180 bottom
FID3 "Fiducial" Fiducial10-30 160,345 r180 bottom
FID4 "Fiducial" Fiducial10-30 3930,140 r180 bottom
FID5 "Fiducial" Fiducial10-30 3929,2070 r0 top
FID6 "Fiducial" Fiducial10-30 3932,138 r0 top
J1 "E6S201-40M LR17-0143" Rosenberger_E6S201-40M_LR17-0143 4360,1336.09 r270 top
J2 "TSW-103-07-G-S" TSW-103-07-G-S 3848.21,1776.09 r90 top
J3 "TSW-103-07-G-S" TSW-103-07-G-S 3250,1050 r0 top
J4 "TSW-101-07-G-S" TSW-101-07-G-S 3151,649 r0 top
J5 "9-2304372-1" TE_1PORT_B1-B 4289.96,534.4 r90 top
J6 "TSW-101-07-G-S" TSW-101-07-G-S 3350,649 r0 top
J7 "901-144-8RFX" AMPHENOL_901-144-8RFX 2735,715 r0 top
J8 "901-144-8RFX" AMPHENOL_901-144-8RFX 3489.57,1981.09 r0 top
J9 "TSW-102-07-G-S" TSW-102-07-G-S 1663,315 r270 top
J12 "7499111614A" Wurth_7499111614A 433,1450.35 r90 top
J14 "TSW-103-07-G-S" TSW-103-07-G-S 760,2019 r0 top
J15 "TSW-103-07-G-S" TSW-103-07-G-S 2199,545 r270 top
J16 "61300111121" WURTH_61300111121 659,1918 r90 top
J17 "61300111121" WURTH_61300111121 859,1918 r0 top
J18 "475890001" Molex_0475890001 1789.2,5.75 r180 bottom
J19 "TSW-102-07-G-S" TSW-102-07-G-S 2490,714 r270 top
J20 "TSW-102-07-G-S" TSW-102-07-G-S 1201.45,1948.82 r180 top
J21 "TSW-102-07-G-S" TSW-102-07-G-S 1900,1950 r180 top
J22 "694106301002" Wurth_694106301002 434.17,660 r90 top
L1 "DLW32MH101XT2" FP-DLW32MH101XT2_1210-MFG 3248,1339 r0 top
L2 "BLM18HE102SN1D" 0603 2499,1514 r270 bottom value="1000 ohm"
L3 "BLM18KG601SH1" "FP-BLM18KG601SH1_0603 (1608 Metric)-MFG" 2883,1294 r90 bottom
L4 "BLM18KG601SH1" "FP-BLM18KG601SH1_0603 (1608 Metric)-MFG" 2617,1165 r0 bottom
L5 "BLM18KG601SH1" "FP-BLM18KG601SH1_0603 (1608 Metric)-MFG" 1756,1226 r180 top
L6 "BLM18KG601SH1" "FP-BLM18KG601SH1_0603 (1608 Metric)-MFG" 1671,1845 r90 top
L7 "BLM18KG601SH1" "FP-BLM18KG601SH1_0603 (1608 Metric)-MFG" 1446,1206 r90 top
L8 "744232090" WE-CNSW_1206 1802,288 r270 bottom
L9 "744053150" WE-TPC-LH 569,201 r90 top value=15uH
L10 "744053150" WE-TPC-LH 3093.21,379.95 r270 top value=15uH
Logo1 "CE Mark" CE_Mark_5mm 1003,247 r180 bottom
Logo2 "FCC disclaimer" FCC_disclaimer 913,82 r0 bottom
Logo3 "Texas Instruments" TI_Stacked_Overlay_Small 3064,419 r180 bottom
Logo4 "WEEE logo" WEEE_Minimum 721,310 r180 bottom
Q1 "BC847CLT1G" SOT-23 1395,1015 r90 bottom value="45 V"
Q2 "BC847CLT1G" SOT-23 2078.77,2056.04 r90 bottom value="45 V"
R1 "CRCW04022K49FKED" 0402 3045,1165 r90 top value=2.49k
R2 "CRCW040226R7FKED" 0402 3024,1410 r180 top value=26.7
R3 "CRCW04022K20JNED" 0402 4073.66,1792.09 r0 bottom value=2.2k
R4 "CRCW04020000Z0EDHP" 0402 2975.16,1359.71 r180 top value=0
R5 "CRCW04022K49FKED" 0402 4032,1686 r0 bottom value=2.49k
R6 "CRCW04020000Z0EDHP" 0402 3470,1360 r0 top value=0
R7 "CRCW04022K20JNED" 0402 4186.87,1686 r180 bottom value=2.2k
R8 "CRCW04020000Z0EDHP" 0402 3470,1360 r0 bottom value=0
R9 "CRCW04020000Z0EDHP" 0402 3470,1313 r0 bottom value=0
R10 "CRCW04020000Z0EDHP" 0402 3470,1313 r0 top value=0
R11 "CRCW04020000Z0EDHP" 0402 2975.16,1317.67 r180 top value=0
R12 "CRCW04022K20JNED" 0402 4186.87,1892.09 r180 bottom value=2.2k
R13 "CRCW040226R7FKED" 0402 3024,1268 r0 top value=26.7
R14 "ERJ-P06F1001V" 0805_HV 3994.99,1297.69 r180 bottom value=1.00k
R15 "ERJ-P06F1001V" 0805_HV 3995,1376 r180 bottom value=1.00k
R16 "CRCW04022K49FKED" 0402 3740,1876.09 r180 bottom value=2.49k
R17 "CRCW04020000Z0EDHP" 0402 2782,1537 r0 bottom value=0
R18 "CRCW08051M00JNEA" 0805_HV 4171.95,1289.3 r180 bottom value=100k
R19 "CRCW04020000Z0EDHP" 0402 2816,1190 r270 bottom value=0
R20 "CRCW04022K20JNED" 0402 3150,950 r270 bottom value=2.2k
R21 "CRCW12061M00JNEA" 1206 4070,954 r0 top value=1.0Meg
R22 "CRCW04020000Z0EDHP" 0402 2468,1350 r90 bottom value=0
R23 "ERJ-P06F1001V" 0805_HV 3715.9,491.09 r180 bottom value=1.00k
R24 "ERJ-P06F1001V" 0805_HV 3716.4,576.09 r180 bottom value=1.00k
R25 "CRCW08051M00JNEA" 0805_HV 3882.28,586.09 r180 bottom value=100k
R26 "ERJ-2GE0R00X" 0402 2735,925 r270 top value=0
R27 "RC0402FR-07470RL" 0402 2691.26,129.98 r90 bottom value=470
R28 "CRCW04021K00FKED" 0402 2487,1142 r90 top value=1.00k
R29 "RT0402BRD0710KL" 0402 2972,1611 r0 top value=10.0k
R30 "CRCW04022K20JNED" 0402 2972,1561 r0 top value=2.2k
R31 "ERJ-2GE0R00X" 0402 2908,1542 r90 bottom value=0
R32 "RC0402FR-07470RL" 0402 1336,1246 r0 bottom value=470
R33 "CRCW04022K49FKED" 0402 1327.62,1666 r0 bottom value=2.49k
R34 "RC0402FR-07470RL" 0402 1329,1800 r180 bottom value=470
R35 "CRCW12061M00JNEA" 1206 530,1395 r0 bottom value=1.0Meg
R36 "CRCW040211K0FKED" 0402 1400,1623.86 r90 bottom value=11.0k
R37 "ERJ-2RKF2201X" 0402 1554,1209 r90 bottom value=2.20k
R38 "CRCW04020000Z0EDHP" 0402 1503.74,1681.56 r90 bottom value=0
R39 "RC0402FR-07470RL" 0402 2300,129.98 r90 bottom value=470
R40 "RC0402FR-07470RL" 0402 2246.24,129.98 r90 bottom value=470
R41 "RC0402FR-07470RL" 0402 2426.53,130 r90 bottom value=470
R42 "RC0402FR-07470RL" 0402 2373.68,130 r90 bottom value=470
R43 "RC0402FR-07470RL" 0402 2558.89,129.12 r90 bottom value=470
R44 "RC0402FR-07470RL" 0402 2501.81,129.1 r90 bottom value=470
R45 "ERJ-2RKF2201X" 0402 760,1914 r270 bottom value=2.20k
R46 "ERJ-2GEJ220X" 0402 1664,740 r90 bottom value=22
R47 "ERJ-2GEJ220X" 0402 1611,740 r90 bottom value=22
R48 "RT0402BRD0710KL" 0402 1204.33,310.46 r270 bottom value=10.0k
R49 "RT0402BRD0710KL" 0402 1306.11,310.46 r270 bottom value=10.0k
R50 "RT0402BRD0710KL" 0402 1406.11,310 r270 bottom value=10.0k
R51 "RT0402BRD0710KL" 0402 1504.92,310 r270 bottom value=10.0k
R52 "CRCW04021K40FKED" 0402 1789.2,478.19 r270 bottom value=1.40k
R53 "RMCF0603FG1M00" 0603 1955,170 r90 top value=1.00Meg
R54 "ERJ-2RKF1004X" 0402 1761.09,458.19 r180 top value=1.00Meg
R55 "RC0402FR-07470RL" 0402 1230,770 r270 bottom value=470
R56 "CRCW04020000Z0EDHP" 0402 1180,930 r90 bottom value=0
R57 "ERJ-2RKF1004X" 0402 1317.3,857.09 r0 bottom value=1.00Meg
R58 "CRCW04020000Z0EDHP" 0402 1235,890 r90 bottom value=0
R59 "CRCW04020000Z0EDHP" 0402 1447.3,727.09 r90 bottom value=0
R60 "CRCW04023K40FKED" 0402 1023.58,310.88 r180 top value=3.40k
R61 "CRCW04022K20JNED" 0402 1540,950 r0 bottom value=2.2k
R62 "CRCW04022K20JNED" 0402 2085,1950 r180 bottom value=2.2k
R63 "CRCW04021K02FKED" 0402 1051.25,231.99 r90 top value=1.02k
R64 "CRCW04021K30FKED" 0402 1780,1070 r270 top value=1.30k
R65 "CRCW04022K20JNED" 0402 1518.62,1065 r0 bottom value=2.2k
R66 "CRCW04022K20JNED" 0402 1950,2105 r180 bottom value=2.2k
R67 "CRCW04022K20JNED" 0402 408.62,383.88 r180 top value=2.2k
R68 "CRCW04024K42FKED" 0402 1780,975 r90 top value=4.42k
R69 "CRCW04022K20JNED" 0402 1203.42,2048.82 r180 bottom value=2.2k
R70 "CRCW04022K26FKED" 0402 2636.28,284.16 r0 top value=2.26k
R71 "CRCW04021K02FKED" 0402 2611.28,362.9 r270 top value=1.02k
R72 "RC0402FR-07470RL" 0402 3240.51,183.52 r0 top value=470
R73 "CRCW040222K0JNED" 0402 390,946.46 r180 top value=22k
R74 "CRCW040222R0JNED" 0402 2769,1614 r270 top value=22
R75 "CRCW040222R0JNED" 0402 2711,1614 r270 top value=22
R76 "CRCW040222R0JNED" 0402 2664,1614 r270 top value=22
R77 "CRCW040222R0JNED" 0402 2617,1614 r270 top value=22
R78 "CRCW040222R0JNED" 0402 2832,1534 r270 top value=22
R79 "CRCW040222R0JNED" 0402 2570,1614 r270 top value=22
R80 "CRCW040222R0JNED" 0402 1939.62,1263 r180 bottom value=22
R81 "CRCW040222R0JNED" 0402 1939.62,1498 r180 bottom value=22
R82 "CRCW040222R0JNED" 0402 1939.62,1451 r180 bottom value=22
R83 "CRCW040222R0JNED" 0402 1939.62,1404 r180 bottom value=22
R84 "CRCW040222R0JNED" 0402 1939.62,1357 r180 bottom value=22
R85 "CRCW040222R0JNED" 0402 1939.62,1310 r180 bottom value=22
R86 "RT0402BRD0710KL" 0402 2521,386 r0 bottom value=10.0k
R87 "RT0402BRD0710KL" 0402 2521,443 r0 bottom value=10.0k
R88 "RT0402BRD0710KL" 0402 2521,501 r0 bottom value=10.0k
R89 "RT0402BRD0710KL" 0402 2521,558 r0 bottom value=10.0k
R90 "CRCW04020000Z0EDHP" 0402 2520,389 r0 top value=0
R91 "CRCW04020000Z0EDHP" 0402 2520,446 r0 top value=0
R92 "CRCW04020000Z0EDHP" 0402 2520,504 r0 top value=0
R93 "CRCW04020000Z0EDHP" 0402 2520,561 r0 top value=0
R94 "CRCW04025K76FKED" 0402 1327,1731 r180 bottom value=5.76k
R95 "CRCW04022K49FKED" 0402 2740,1714 r90 bottom value=2.49k
R96 "CRCW04020000Z0EDHP" 0402 2871,1001 r315 top value=0
R97 "CRCW0402100RFKED" 0402 2688,1185 r45 top value=100
R98 "CRCW04020000Z0EDHP" 0402 3104,925 r270 top value=0
R99 "RC0402FR-07470RL" 0402 2634.18,129.98 r90 bottom value=470
R100 "CRCW04020000Z0EDHP" 0402 2571,1472 r180 bottom value=0
R101 "CRCW04022K20JNED" 0402 3227,825 r90 top value=2.2k
R102 "CRCW04022K20JNED" 0402 3285,825 r270 top value=2.2k
R103 "ERJ-2GE0R00X" 0402 2871,1567 r90 top value=0
R104 "ERJ-2GE0R00X" 0402 2910,1568 r90 top value=0
S1 "219-4LPST" SW_219-4LPST 1336,299 r90 top
S2 "KSR221GLFS" KSR 1350,748.9 r180 top
TP1 "TP_SM_1MM" TP_SM_1MM 1620,565 r90 bottom
TP2 "TP_SM_1MM" TP_SM_1MM 1620,490 r90 bottom
TP3 "TP_SM_1MM" TP_SM_1MM 1765,800 r90 bottom
TP4 "TP_SM_1MM" TP_SM_1MM 1845,800 r90 bottom
TP5 "TP_SM_1MM" TP_SM_1MM 1890,875 r90 bottom
TP6 "TP_SM_1MM" TP_SM_1MM 1935,800 r90 bottom
TP7 "TP_SM_1MM" TP_SM_1MM 1545,523 r90 bottom
TP8 "1502-2" Keystone1502-2 975,560 r0 top
TP9 "1502-2" Keystone1502-2 415,2050 r90 top
U1 "TPD2E2U06QDCKRQ1" DCK0003A_N 3098,1339 r0 top
U2 "DP83TG720SWRNDRQ1" RND0036A 2703.32,1367.83 r90 top
U3 "DP83867ERGZR" RGZ0048B 1600.16,1458.62 r0 bottom
U4 "MSP430F5528IRGCT" RGC0064B 1913.43,680 r180 top
U5 "TPS3838K33QDBVRQ1" DBV0005A_N 1341.08,707.09 r180 bottom
U6 "LMR14206XMKX/NOPB" DDC0006A_N 939.86,214.14 r180 top
U7 "TPS74701DRCR" DRC0010J 1675,1045 r0 top locked
U8 "LMR14206XMKX/NOPB" DDC0006A_N 2727.15,382.98 r0 top
U9 "TVS3300DRVR" DRV0006A#1 765,840 r90 bottom
U10 "TPS7B8133QDRVRQ1" DRV0006A#2 2987,1025 r180 top
Y1 "ABM8AIG-25.000MHZ-12-2Z-T3" Abracon_ABM8AIG 2604,1062 r180 top
Y2 "NX5032GA-25.000M-STD-CSK-4" NDK_NX5032GA 1524.53,1809.98 r180 bottom
Y3 "CSTCR4M00G15L99-R0" Murata_CSTCR_G15L 1934.88,372.7 r0 top

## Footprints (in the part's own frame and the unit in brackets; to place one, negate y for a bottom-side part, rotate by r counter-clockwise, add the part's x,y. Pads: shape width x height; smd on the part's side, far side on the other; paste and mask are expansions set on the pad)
0402 [mm] "0402 from SM-752 data"
  rect 0.8x0.6 smd: 1(-0.6,0) 2(0.6,0)
  silkscreen extent -1.22,-0.52 1.22,0.52, body extent -0.55,-0.3 0.55,0.3, height 0.6
0402_065 [mm] "0402"
  rect 0.8x0.6 smd: 1(-0.6,0) 2(0.6,0)
  silkscreen extent -1.22,-0.52 1.22,0.52, body extent -0.55,-0.3 0.55,0.3, height 0.65
0402S [mil] "Based on C0402S footprint from PADS legacy"
  rect 15x24 smd: 1(-20,0) 2(20,0)
  body extent -22,-12 22,12, height 24
0603 [mm] "0603 from SM-752 data"
  rect 1x0.95 smd: 1(-0.8,0) 2(0.8,0)
  silkscreen extent -1.52,-0.69 1.52,0.69, body extent -0.87,-0.47 0.87,0.47, height 1
0805_HV [mil] "0805 with 30mil clearance between pads"
  rect 50x63 smd: 1(-40,0) 2(40,0)
  silkscreen extent -74,-40 74,40, body extent -43,-29 43,29, height 57
1206 [mm] "1206 from SM-752 data"
  rect 1.3x1.85 smd: 1(-1.45,0) 2(1.45,0)
  silkscreen extent -2.4,-1.21 2.4,1.21, body extent -1.7,-0.9 1.7,0.9, height 1.35
Abracon_ABM8AIG [mm] "SMD, 4-Leads, Body 3.2x2.5mm"
  rrect9% 1.1x1.3 smd: 1(-0.95,1.15) 2(-0.95,-1.15) 3(0.95,-1.15) 4(0.95,1.15)
  silkscreen extent -1.8,1.3 -1.28,2.07, body extent -1.3,-1.65 1.3,1.65, height 0.8
AMPHENOL_901-144-8RFX [mm] "SMA Straight Jack, TH"
  round 2 hole 1.5: 1(0,0)
  round 2.2 hole 1.7: 2(-2.54,2.54) 3(-2.54,-2.54) 4(2.54,-2.54) 5(2.54,2.54)
  silkscreen extent -3.7,-3.7 3.7,3.7, body extent -3.7,-3.7 3.7,3.7, height 9.93
CAPSMT_62_F80 [mm] "6.3 x 7.7mm:  Chemi-Con F80"
  rect 3.5x1.6 smd: 1(-2.7,0) 2(2.7,0)
  silkscreen extent -3.36,-3.4 3.44,3.4, body extent -3.4,-3.4 3.44,3.4, height 8
CE_Mark_5mm [mil] "Minimum text height for CE Mark"
  silkscreen extent -138,-98 138,98
DBV0005A_N [mm] "SOT23, 5-Leads, Body 2.9x1.6mm, Pitch 0.95mm, Lead Span 2.8mm, IPC Medium Density"
  rrect17% 1x0.6 smd: 1(-1.375,0.95) 2(-1.375,0) 3(-1.375,-0.95) 4(1.375,-0.95) 5(1.375,0.95)
  silkscreen extent -0.25,-1.55 0.25,1.55, body extent -1.42,-1.46 1.42,1.46, height 1.09
DCK0003A_N [mm] "SOT23, 3-Leads, Body 2.0x1.25mm, Pitch 0.65mm, Lead Span 2.1mm, IPC Medium Density"
  rrect25% 0.85x0.4 smd: 1(-1.125,0.65) 2(-1.125,-0.65) 3(1.125,0)
  silkscreen extent -1.02,-1.1 0.7,1.52, body extent -1.06,-1 1.06,1, height 1.1
DDC0006A_N [mm]
  rrect17% 1x0.6 smd: 1(-1.375,0.95) 2(-1.375,0) 3(-1.375,-0.95) 4(1.375,-0.95) 5(1.375,0) 6(1.375,0.95)
  silkscreen extent -1.75,-1.52 0.7,1.53, body extent -1.43,-1.48 1.43,1.49, height 0.92
DRC0010J [mm] "VSON-10"
  rrect42% 0.6x0.24 smd: 1(-1.4,1) 2(-1.4,0.5) 3(-1.4,0) 4(-1.4,-0.5) 5(-1.4,-1) 6(1.4,-1) 7(1.4,-0.5) 8(1.4,0) 9(1.4,0.5) 10(1.4,1)
  rrect12% 1.65x2.4 smd paste-1 mask-2: 11(0,0)
  Top Layer region: -0.375,-1.65 -0.375,-1.2 -0.775,-1.2 -0.794,-1.196 -0.81,-1.185 -0.821,-1.169 -0.825,-1.15 -0.825,-1.15 -0.825,1.15 -0.821,1.169 -0.81,1.185 -0.794,1.196 -0.775,1.2 -0.775,1.2 -0.375,1.2 -0.375,1.65 -0.371,1.669 -0.36,1.685 -0.344,1.696 -0.325,1.7 -0.325,1.7 -0.325,1.7 -0.175,1.7 -0.175,1.7 -0.156,1.696 -0.14,1.685 -0.129,1.669 -0.125,1.65 -0.125,1.65 -0.125,1.2 0.125,1.2 0.125,1.65 0.129,1.669 0.14,1.685 0.156,1.696 0.175,1.7 0.175,1.7 0.175,1.7 0.325,1.7 0.325,1.7 0.344,1.696 0.36,1.685 0.371,1.669 0.375,1.65 0.375,1.65 0.375,1.2 0.775,1.2 0.794,1.196 0.81,1.185 0.821,1.169 0.825,1.15 0.825,1.15 0.825,-1.15 0.821,-1.169 0.81,-1.185 0.794,-1.196 0.775,-1.2 0.775,-1.2 0.375,-1.2 0.375,-1.65 0.371,-1.669 0.36,-1.685 0.344,-1.696 0.325,-1.7 0.325,-1.7 0.175,-1.7 0.156,-1.696 0.14,-1.685 0.129,-1.669 0.125,-1.65 0.125,-1.65 0.125,-1.2 -0.125,-1.2 -0.125,-1.65 -0.129,-1.669 -0.14,-1.685 -0.156,-1.696 -0.175,-1.7 -0.175,-1.7 -0.325,-1.7 -0.344,-1.696 -0.36,-1.685 -0.371,-1.669 -0.375,-1.65
  body extent -1.5,-1.5 1.5,1.5, height 1
DRV0006A#1 [mm] "SON, 6-Leads, Body 2x2mm, Pitch 0.65mm, Thermal Pad 1.6x1mm, TI Recommended"
  rrect33% 0.45x0.3 smd: 1(-0.975,0.65) 2(-0.975,0) 3(-0.975,-0.65) 4(0.975,-0.65) 5(0.975,0) 6(0.975,0.65)
  rrect14% 1x0.7 on Bottom Paste: 7(0,-0.45) 7(0,0.45)
  rrect10% 1x1.6 smd paste-0.5: 7(0,0)
  silkscreen extent -1.05,-1.2 1.05,1.2, body extent -1.05,-1.05 1.05,1.05, height 0.81
DRV0006A#2 [mm] "SON, 6-Leads, Body 2x2mm, Pitch 0.65mm, Thermal Pad 1.6x1mm, TI Recommended"
  rrect33% 0.45x0.3 smd: 1(-0.975,0.65) 2(-0.975,0) 3(-0.975,-0.65) 4(0.975,-0.65) 5(0.975,0) 6(0.975,0.65)
  rrect14% 1x0.7 on Top Paste: 7(0,0.45) 7(0,-0.45)
  rrect10% 1x1.6 smd paste-0.5: 7(0,0)
  silkscreen extent -1.05,-1.2 1.05,1.2, body extent -1.05,-1.05 1.05,1.05, height 0.81
FCC_disclaimer [mil]
Fiducial10-30 [mm]
  round 1 smd mask+1: 1(0,0)
  Top Layer keep-out circle w1.678: c0,0 r0.75
"FP-BLM18KG601SH1_0603 (1608 Metric)-MFG" [mm]
  rrect15% 0.65x0.7 smd paste+0 mask+0: 1(-0.675,0) 2(0.675,0)
  silkscreen extent -0.87,-0.75 0.87,0.75, body extent -0.8,-0.4 0.8,0.4, height 0.95
FP-DLW32MH101XT2_1210-MFG [mm]
  rrect17% 1.05x0.6 smd paste+0 mask+0: 1(-1.525,-0.5) 2(1.525,-0.5) 3(1.525,0.5) 4(-1.525,0.5)
  silkscreen extent -2.72,-1.35 1.7,1.35, body extent -2.15,-1.45 2.15,1.45, height 0.25
HSMF-C165_RG [mm] "SMD, 4-Leads, Body 1.6x0.8mm"
  rect 0.7x0.4 smd: 1(-0.65,0.35) 2(-0.65,-0.35) 3(0.65,0.35) 4(0.65,-0.35)
  silkscreen extent -1,-0.8 1.5,0.8, body extent -0.85,-0.45 0.85,0.45, height 0.51
Keystone1502-2 [mm] "Double Turret"
  round 3.5 hole 2.5: 1(0,0)
  silkscreen extent -2.3,-2.3 2.3,2.3, body extent -1.6,-1.6 1.59,1.6, height 5.62
KSR [mm] "C&K Components SPST switch"
  rect 1.5x1.4 smd: 1(-3.25,0) 2(3.25,0)
  silkscreen extent -3.2,-2 3.2,2, body extent -3,-1.9 3,1.9, height 2.65
Molex_0475890001 [mm] "Molex"
  rrect25% 0.4x1.35 smd: 1(-1.3,4.125) 2(-0.65,4.125) 3(0,4.125) 4(0.65,4.125) 5(1.3,4.125)
  oval 1.05x1.3 hole 0.7 slot 0.85 at 90 deg: 6(2.225,4.45) 11(-2.225,4.45)
  oval 0.8x2 hole 0.6 slot 1.3 at 90 deg: 7(4.175,1.45) 10(-4.175,1.45)
  rrect6% 1.8x2 smd: 8(1.15,1.45) 9(-1.15,1.45)
  Top Layer region: 2.6,0.45 2.6,2.45 4.175,2.45 4.175,0.45
  Top Layer region: -4.175,0.45 -4.175,2.45 -2.6,2.45 -2.6,0.45
  silkscreen extent -3.75,2.85 3.75,4.3, body extent -4.32,-1.3 4.33,4.59, height 2.81
Murata_CSTCR_G15L [mm] "Murata"
  rrect25% 0.4x2.6 smd: 1(-1.5,0) 2(0,0) 3(1.5,0)
  body extent -2.3,-1.05 2.3,1.05, height 1.2
NDK_NX5032GA [mm] "SMD, 2-Leads Body 5x3.2mm"
  rect 2x2.4 smd: 1(-2,0) 2(2,0)
  silkscreen extent -2.6,-1.7 2.6,1.7, body extent -2.6,-1.7 2.6,1.7, height 1.5
RGC0064B [mm] "VQFN-64"
  rrect42% 0.6x0.24 smd mask+0.07: 1(-4.4,3.75) 2(-4.4,3.25) 3(-4.4,2.75) 4(-4.4,2.25) 5(-4.4,1.75) 6(-4.4,1.25) 7(-4.4,0.75) 8(-4.4,0.25) 9(-4.4,-0.25) 10(-4.4,-0.75) 11(-4.4,-1.25) 12(-4.4,-1.75) 13(-4.4,-2.25) 14(-4.4,-2.75) 15(-4.4,-3.25) 16(-4.4,-3.75) 33(4.4,-3.75) 34(4.4,-3.25) 35(4.4,-2.75) 36(4.4,-2.25) 37(4.4,-1.75) 38(4.4,-1.25) 39(4.4,-0.75) 40(4.4,-0.25) 41(4.4,0.25) 42(4.4,0.75) 43(4.4,1.25) 44(4.4,1.75) 45(4.4,2.25) 46(4.4,2.75) 47(4.4,3.25) 48(4.4,3.75)
  rrect42% 0.24x0.6 smd mask+0.07: 17(-3.75,-4.4) 18(-3.25,-4.4) 19(-2.75,-4.4) 20(-2.25,-4.4) 21(-1.75,-4.4) 22(-1.25,-4.4) 23(-0.75,-4.4) 24(-0.25,-4.4) 25(0.25,-4.4) 26(0.75,-4.4) 27(1.25,-4.4) 28(1.75,-4.4) 29(2.25,-4.4) 30(2.75,-4.4) 31(3.25,-4.4) 32(3.75,-4.4) 49(3.75,4.4) 50(3.25,4.4) 51(2.75,4.4) 52(2.25,4.4) 53(1.75,4.4) 54(1.25,4.4) 55(0.75,4.4) 56(0.25,4.4) 57(-0.25,4.4) 58(-0.75,4.4) 59(-1.25,4.4) 60(-1.75,4.4) 61(-2.25,4.4) 62(-2.75,4.4) 63(-3.25,4.4) 64(-3.75,4.4)
  rrect2% 4.25x4.25 smd paste-2.112: 65(0,0)
  body extent -4.5,-4.5 4.5,4.5, height 1
RGZ0048B [mm] "QFN, 48-Leads, Body 7x7mm, Pitch 0.5mm, Thermal Pad 5.15x5.15mm, TI Recommended"
  rrect42% 0.6x0.24 smd: 1(-3.4,2.75) 2(-3.4,2.25) 3(-3.4,1.75) 4(-3.4,1.25) 5(-3.4,0.75) 6(-3.4,0.25) 7(-3.4,-0.25) 8(-3.4,-0.75) 9(-3.4,-1.25) 10(-3.4,-1.75) 11(-3.4,-2.25) 12(-3.4,-2.75) 25(3.4,-2.75) 26(3.4,-2.25) 27(3.4,-1.75) 28(3.4,-1.25) 29(3.4,-0.75) 30(3.4,-0.25) 31(3.4,0.25) 32(3.4,0.75) 33(3.4,1.25) 34(3.4,1.75) 35(3.4,2.25) 36(3.4,2.75)
  rrect42% 0.24x0.6 smd: 13(-2.75,-3.4) 14(-2.25,-3.4) 15(-1.75,-3.4) 16(-1.25,-3.4) 17(-0.75,-3.4) 18(-0.25,-3.4) 19(0.25,-3.4) 20(0.75,-3.4) 21(1.25,-3.4) 22(1.75,-3.4) 23(2.25,-3.4) 24(2.75,-3.4) 37(2.75,3.4) 38(2.25,3.4) 39(1.75,3.4) 40(1.25,3.4) 41(0.75,3.4) 42(0.25,3.4) 43(-0.25,3.4) 44(-0.75,3.4) 45(-1.25,3.4) 46(-1.75,3.4) 47(-2.25,3.4) 48(-2.75,3.4)
  rrect9% 1.17x1.17 on Bottom Paste: 49(-1.37,-1.37) 49(-1.37,0) 49(-1.37,1.37) 49(0,-1.37) 49(0,0) 49(0,1.37) 49(1.37,-1.37) 49(1.37,0) 49(1.37,1.37)
  rrect2% 4.1x4.1 smd paste-2.575: 49(0,0)
  silkscreen extent -3.72,-3.72 3.72,3.72, body extent -3.5,-3.5 3.5,3.5, height 1.01
RND0036A [mm] "TI"
  oval 0.6x0.25 smd: 1(-2.9,2) 2(-2.9,1.5) 3(-2.9,1) 4(-2.9,0.5) 5(-2.9,0) 6(-2.9,-0.5) 7(-2.9,-1) 8(-2.9,-1.5) 9(-2.9,-2) 19(2.9,-2) 20(2.9,-1.5) 21(2.9,-1) 22(2.9,-0.5) 23(2.9,0) 24(2.9,0.5) 25(2.9,1) 26(2.9,1.5) 27(2.9,2)
  oval 0.25x0.6 smd: 10(-2,-2.9) 11(-1.5,-2.9) 12(-1,-2.9) 13(-0.5,-2.9) 14(0,-2.9) 15(0.5,-2.9) 16(1,-2.9) 17(1.5,-2.9) 18(2,-2.9) 28(2,2.9) 29(1.5,2.9) 30(1,2.9) 31(0.5,2.9) 32(0,2.9) 33(-0.5,2.9) 34(-1,2.9) 35(-1.5,2.9) 36(-2,2.9)
  rect 3.7x3.7 smd paste-1.85: 37(0,0)
  silkscreen extent -3.17,-3.18 3.18,3.2, body extent -3,-3 3,3, height 0.81
Rosenberger_E6S201-40M_LR17-0143 [mm] "Connector, 2 Pos, TH"
  round 1.2 hole 0.7: 1(-1,-11.87) 2(1,-11.87)
  round 2.2 hole 1.62: S1(-3.5,-10) S2(-3.5,-17.5) S3(3.5,-10) S4(3.5,-17.5)
  rrect10% 2.2x1 smd: S5(0,-9.27)
  rrect12% 0.8x0.8 smd: S6(-3.7,-12.97) S7(3.7,-12.97)
  Top Layer region: 4.65,-13.87 4.65,-11.67 2.99,-11.67 2.99,-11.67 2.856,-12.615 2.3,-13.39 2.3,-13.39 2.3,-13.87
  Top Layer region: -4.65,-13.87 -4.65,-11.67 -2.99,-11.67 -2.99,-11.67 -2.856,-12.615 -2.3,-13.39 -2.3,-13.39 -2.3,-13.87
  Top Layer keep-out region: 4.65,-17.01 4.65,-15.27 2.3,-15.27 2.3,-17.15 2.607,-16.626 3.125,-16.308 3.731,-16.272 4.283,-16.526 4.65,-17.01
  Top Layer keep-out region: 2.252,-10.07 2.362,-9.483 2.732,-9.014 3.277,-8.77 3.277,-8.77 1.35,-8.77 1.35,-10.07
  Top Layer keep-out region: -2.252,-10.07 -2.362,-9.483 -2.732,-9.014 -3.277,-8.77 -3.277,-8.77 -1.35,-8.77 -1.35,-10.07
  Top Layer keep-out region: -4.65,-17.01 -4.65,-15.27 -2.3,-15.27 -2.3,-17.15 -2.607,-16.626 -3.125,-16.308 -3.731,-16.272 -4.283,-16.526 -4.65,-17.01
  body extent -5.5,-18.9 5.5,3, height 12.8
SMA [mm] "Molded Diode, 2-Leads, Body 4.3x2.6mm, IPC Medium Density, based on OnSemi component dimensions and land pattern"
  rect 2x2 smd: 1(-2,0) 2(2,0)
  silkscreen extent -3.66,-1.57 2.79,1.57, body extent -2.6,-1.3 2.6,1.3, height 2.42
SOT-23 [mm] "SOT23, 3-Leads, Body 2.9x1.3mm, Pitch 0.95mm, Lead Span 2.5mm, IPC Medium Density"
  rrect50% 1x0.6 smd: 1(-1.2,0.95) 2(-1.2,-0.95) 3(1.2,0)
  silkscreen extent -1.62,-1.5 0.7,1.5, body extent -1.16,-1.45 1.21,1.45, height 1
SW_219-4LPST [mil] "SMD, 8-Leads, Body 11.93x6.95mm, Pitch 2.54mm"
  rect 96x44 smd: 1(-169.5,150) 2(-169.5,50) 3(-169.5,-50) 4(-169.5,-150) 5(169.5,-150) 6(169.5,-50) 7(169.5,50) 8(169.5,150)
  silkscreen extent -171,-229 132,229, body extent -195,-229 195,229, height 169
TE_1PORT_B1-B [mm] "Header, 1.8mm, 2x1, TH"
  rect 1.5x1.5 hole 1: 1(-0.9,17.35)
  round 1.5 hole 1: 2(0.9,17.35)
  round 0 hole 2.2 unplated: MH1(0,3.35) MH2(6.6,3.35)
  round 0 hole 1.6 unplated: MH3(6.35,11.75) MH4(0,0)
  oval 1.5x2.3 hole 1 slot 1.775 at 90 deg: S1(-3.9,16.963) S4(3.9,16.963)
  oval 1.5x2.4 hole 1 slot 1.89 at 90 deg: S2(-3.9,9.905) S5(3.9,9.905)
  oval 1.5x2.5 hole 1 slot 2 at 90 deg: S3(-3.9,2.85) S6(3.9,2.85)
  silkscreen extent -7.45,-1.8 10.3,20, body extent -7.45,-1.8 10.3,19.3, height 13.5
TI_Stacked_Overlay_Small [mil]
  silkscreen extent -418,-98 418,98
TP_SM_1MM [mm] "1mm Test Point, SMT"
  round 1 smd paste-0.5: 1(0,0)
TSW-101-07-G-S [mm] "Samtec 100mil, 1pos, 230 mil above insulator"
  rrect6% 1.65x1.65 hole 1.016: 1(0,0)
  silkscreen extent -1.27,-1.27 1.27,1.27, body extent -1.27,-1.27 1.27,1.27, height 8.38
TSW-102-07-G-S [mm] "Samtec 100mil, 1x2, 230 mil above insulator"
  rrect50% 1.65x1.65 hole 1.016: 1(-1.27,0)
  round 1.65 hole 1.016: 2(1.27,0)
  silkscreen extent -3.17,-1.27 2.54,1.27, body extent -2.54,-1.27 2.54,1.27, height 8.38
TSW-103-07-G-S [mm] "Samtec 100mil, 1x3, 230 mil above insulator"
  rrect50% 1.65x1.65 hole 1.016: 1(-2.54,0)
  round 1.65 hole 1.016: 2(0,0) 3(2.54,0)
  body extent -3.81,-1.27 3.81,1.27, height 8.38
WE-CNSW_1206 [mm] "SMD, 4-Leads, Body 3.2x1.6mm"
  rect 1.1x0.6 smd: 1(-1.35,0.5) 2(1.35,0.5) 3(1.35,-0.5) 4(-1.35,-0.5)
  silkscreen extent -1.5,-0.8 0.4,1.3, body extent -1.6,-0.8 1.6,0.8, height 1.91
WE-TPC-LH [mm] "Wurth Elektronik recommended land pattern, 2009-01-15"
  rect 0.5x0.5 smd: 1(-2.7,0) 2(2.7,0)
  Top Layer region: 0.95,3.15 0.95,3.15 0.95,1.987 1.228,1.838 1.563,1.563 1.838,1.228 2.042,0.846 2.168,0.431 2.211,0 2.168,-0.431 2.042,-0.846 1.838,-1.228 1.563,-1.563 1.228,-1.838 0.95,-1.987 0.95,-3.15 3.15,-3.15 3.15,-3.15 3.15,3.15 0.95,3.15
  Top Layer region: -0.95,3.15 -0.95,3.15 -0.95,1.987 -1.228,1.838 -1.563,1.563 -1.838,1.228 -2.042,0.846 -2.168,0.431 -2.211,0 -2.168,-0.431 -2.042,-0.846 -1.838,-1.228 -1.563,-1.563 -1.228,-1.838 -0.95,-1.987 -0.95,-3.15 -3.15,-3.15 -3.15,-3.15 -3.15,3.15 -0.95,3.15
  silkscreen extent -3.4,-3.4 3.4,3.4, body extent -3.05,-3.05 3.05,3.05, height 3
WEEE_Minimum [mil] "WEEElie bin"
  silkscreen extent -95,-172 99,104
WL-SMCC_0402_Green [mm] "SMD, 2-Leads, Body 1x0.5mm"
  rrect17% 0.6x0.6 smd: 1(-0.55,0) 2(0.55,0)
  body extent -0.5,-0.25 0.5,0.25, height 0.39
WL-SMCW_RED [mm] "WURTH"
  rect 0.8x0.8 smd: 1(-0.8,0) 2(0.8,0)
  silkscreen extent -1.9,-0.8 1.2,0.8, body extent -0.85,-0.45 0.85,0.45, height 0.8
Wurth_7499111614A [mm] "Connector, 1 Port RJ45, Gold, R/A, TH"
  rrect50% 1.35x1.35 hole 0.9: 1(-5.075,-15.24)
  round 1.35 hole 0.9: 2(-3.045,-15.24) 3(-1.015,-15.24) 4(1.015,-15.24) 5(3.045,-15.24) 6(5.075,-15.24) 7(-6.085,-17.78) 8(-4.055,-17.78) 9(-2.025,-17.78) 10(2.025,-17.78) 11(4.055,-17.78) 12(6.085,-17.78)
  round 1.53 hole 1.02: 13(-6.09,-20.32) 14(-3.55,-20.32) 15(3.55,-20.32) 16(6.09,-20.32)
  round 2.85 hole 3.15 unplated mask+0.102: ALIGN1(-6.35,0) ALIGN2(6.35,0)
  round 2.4 hole 1.6: S1(-8.065,3.18) S2(8.065,3.18)
  body extent -9.68,-22.13 9.69,10.89, height 15.79
WURTH_61300111121 [mm] "Header, 2.54 mm, 1x1, TH"
  rect 1.65x1.65 hole 1.15: 1(0,0)
  silkscreen extent -1.27,-1.27 1.27,1.27, body extent -1.27,-1.27 1.27,1.27, height 8.54
Wurth_694106301002 [mm] "WR-DC DC Power Jack, R/A, TH"
  rect 3.5x1.3 hole 0.8 slot 3 at 0 deg: 1(0,-2.9) 2(0,2.9)
  rect 1.3x3.5 hole 0.8 slot 3 at 90 deg: 3(-4.8,0.1)
  silkscreen extent -4.5,-4.1 4.5,10.7, body extent -4.9,-3.8 4.5,10.7, height 10.63

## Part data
C1 C6: library part CMP-0006467-2, "CAP, CERM, 47 pF, 50 V, +/- 1%, C0G/NP0, 0402", Cap_Case=0402, Manufacturer=MuRata, Supplier Part Number 1=490-6241-1-ND, TempCo=C0G/NP0, Tolerance_%=1%, Value1=Unknown, Value2=50V, ValueDisplayed=47pF
C2 C5 C30 C31: library part CMP-0006438-2, "CAP, CERM, 22 pF, 50 V, +/- 1%, C0G/NP0, 0402", Cap_Case=0402, Manufacturer=MuRata, Supplier Part Number 1=490-8589-1-ND, TempCo=C0G/NP0, Tolerance_%=1%, Value1=Unknown, Value2=50V, ValueDisplayed=22pF
C3 C4: library part CMP-0006201-2, "CAP, CERM, 0.1 uF, 16 V, +/- 10%, X7R, 0402", Cap_Case=0402, Manufacturer=AVX, Supplier Part Number 1=478-7888-1-ND, TempCo=X7R, Tolerance_%=10%, Value1=Unknown, Value2=16V, ValueDisplayed=0.1uF
C7 C28: library part CMP-0008920-2, "CAP, CERM, 4700 pF, 1000 V, +/- 10%, X7R, 1206", Cap_Case=1206, Manufacturer=MuRata, Supplier Part Number 1=490-3498-1-ND, TempCo=X7R, Tolerance_%=10%, Value1=Unknown, Value2=1000V, ValueDisplayed=4700pF
C8 C36 C70: library part CMP-0085177-1, "CAP, CERM, 0.01 µF, 1000 V,+/- 10%, X7R, 1206", Cap_Case=1206, Manufacturer=Kemet, TempCo=X7R, Tolerance_%=10%, Value2=1000V, ValueDisplayed=0.01µF
C9 C10 C14 C16 C18 C22 C29 C37 C38 C41 C42 C47 C49 C51 C53 C57 C59 C61 C65 C67 C69 C77 C79 C80 C81 C82 C88: library part CMP-0006279-2, "CAP, CERM, 0.1 uF, 50 V, +/- 10%, X5R, 0402", Cap_Case=0402, Manufacturer=TDK, Supplier Part Number 1=445-5942-1-ND, TempCo=X5R, Tolerance_%=10%, Value1="0.039064 ohm", Value2=50V, ValueDisplayed=0.1uF
C11 C12 C19 C20 C24 C25 C45 C55 C63 C78 C85: library part CMP-0006564-2, "CAP, CERM, 10 uF, 10 V, +/- 20%, X5R, 0402", Cap_Case=0402, Manufacturer=MuRata, TempCo=X5R, Tolerance_%=20%, Value1=Unknown, Value2=10V, ValueDisplayed=10uF
C13 C21 C26 C34: library part CMP-0006263-2, "CAP, CERM, 2.2 uF, 10 V, +/- 10%, X5R, 0402", Cap_Case=0402, Manufacturer=TDK, Supplier Part Number 1=445-7392-1-ND, TempCo=X5R, Tolerance_%=10%, Value1=Unknown, Value2=10V, ValueDisplayed=2.2uF
C15 C17 C23 C27 C33 C48 C50 C52 C54 C58 C60 C62 C66 C68: library part CMP-0006561-2, "CAP, CERM, 0.01 uF, 10 V, +/- 10%, X5R, 0402", Cap_Case=0402, Manufacturer=MuRata, Supplier Part Number 1=GRM155R61A103KA01D-ND, TempCo=X5R, Tolerance_%=10%, Value1=Unknown, Value2=10V, ValueDisplayed=0.01uF
C32: library part CMP-0007007-5, "CAP, CERM, 10 uF, 25 V, +/- 20%, X5R, 0603", Cap_Case=0603, Manufacturer=TDK, Supplier Part Number 1=445-9015-1-ND, TempCo=X5R, Tolerance_%=20%, Value1="0.004639 ohm", Value2=25V, ValueDisplayed=10uF
C35 C39: library part CMP-0007020-5, "CAP, CERM, 2.2 uF, 35 V, +/- 10%, X5R, 0603", Cap_Case=0603, Manufacturer=TDK, Supplier Part Number 1=445-8025-1-ND, TempCo=X5R, Tolerance_%=10%, Value1="0.007674 ohm", Value2=35V, ValueDisplayed=2.2uF
C43 C44: library part CMP-0077091-1, "CAP, CERM, 27 pF, 25 V,+/- 5%, C0G/NP0, 0402", Cap_Case=0402, Manufacturer=MuRata, Supplier Part Number 1=490-6176-1-ND, TempCo=C0G/NP0, Tolerance_%=5%, Value2=25V, ValueDisplayed=27pF
C46 C56 C64 C86 C87: library part CMP-0006608-2, "CAP, CERM, 1 uF, 25 V, +/- 10%, X5R, 0402", Cap_Case=0402, Manufacturer=MuRata, Supplier Part Number 1=490-10017-1-ND, TempCo=X5R, Tolerance_%=10%, Value1=Unknown, Value2=25V, ValueDisplayed=1uF
C71 C72: library part CMP-0064916-2, "CAP, CERM, 10 pF, 50 V,+/- 1%, C0G/NP0, 0402", Cap_Case=0402, Manufacturer=MuRata, Supplier Part Number 1=490-6186-1-ND, TempCo=C0G/NP0, Tolerance_%=1%, Value1=Unknown, Value2=50V, ValueDisplayed=10pF
C73: library part CMP-0006268-2, "CAP, CERM, 4.7 uF, 10 V, +/- 10%, X5R, 0402", Cap_Case=0402_065, Manufacturer=TDK, Supplier Part Number 1=445-13820-1-ND, TempCo=X5R, Tolerance_%=10%, Value1="0.003417 ohm", Value2=10V, ValueDisplayed=4.7uF
C74 C76: library part CMP-0006570-2, "CAP, CERM, 0.22 uF, 10 V, +/- 10%, X5R, 0402", Cap_Case=0402, Manufacturer=MuRata, Supplier Part Number 1=490-3910-1-ND, TempCo=X5R, Tolerance_%=10%, Value1=Unknown, Value2=10V, ValueDisplayed=0.22uF
C75: library part CMP-0006199-2, "CAP, CERM, 0.47 uF, 6.3 V, +/- 10%, X5R, 0402", Cap_Case=0402, Manufacturer=AVX, Supplier Part Number 1=478-6196-1-ND, TempCo=X5R, Tolerance_%=10%, Value1=Unknown, Value2=6.3V, ValueDisplayed=0.47uF
C83 C89: library part CMP-0007825-2, "CAP, CERM, 47 uF, 10 V, +/- 20%, X5R, 0805", Cap_Case=0805, Manufacturer=TDK, Supplier Part Number 1=445-8239-1-ND, TempCo=X5R, Tolerance_%=20%, Value1="0.00294 ohm", Value2=10V, ValueDisplayed=47uF
C91: library part CMP-0010800-1, "CAP, AL, 100 uF, 35 V, +/- 20%, SMD", Cap_Case=F80, Manufacturer=Chemi-Con, Supplier Part Number 1=565-2119-1-ND, Tolerance_%=20%, Value1=Unknown, Value2=35V, ValueDisplayed=100uF
D1 D5 D6 D7: library part CMP-0086344-1, "Diode, TVS, Bi, AEC-Q101, 0603", Manufacturer=Panasonic
D2 D3 D4 D13 D14 D16 D17 D19 D21: library part CMP-0081765-2, "LED, Green, SMD", Color=Green, Manufacturer="Wurth Elektronik", Power_TotalModule=99mW, Value1=0.099W, Value2=3.2V
D8 D9 D10 D22: library part CMP-0002934-2, "LED, Rg, SMD", Color=RG, Manufacturer=Avago, Supplier Part Number 1=516-1419-1-ND, Value1=W, Value2=2.2V
D11 D20: library part CMP-0028762-2, "Diode, Schottky, 60 V, 1 A, AEC-Q101, SMA", Manufacturer="ON Semiconductor", Value1=1A, Value2=0.51V
D12: library part CMP-0002947-3, "LED, Red, SMD", Color=Red, Manufacturer="Wurth Elektronik", Power_TotalModule=72mW, Value1=0.072W, Value2=2V
D15 D18: library part CMP-0028389-2, "Diode, Schottky, 60 V, 1 A, SMA", Manufacturer="Diodes Inc.", Value1=1A, Value2=0.7V
F1: library part CMP-0003452-2, "Fuse, 0.5 A, 63VAC/VDC, SMD", Irating_A=500mA, Manufacturer=Littelfuse, Supplier Part Number 1=F1602CT-ND
FID1 FID2 FID3 FID4 FID5 FID6: library part CMP-0077181-1, "Fiducial mark.  There is nothing to buy or mount.", Manufacturer=N/A
J1: library part CMP-0084194-1, "Connector, 2 Pos, TH", Current_A=500mA, Manufacturer=Rosenberger, Voltage_V=50V
J2 J3 J14 J15: library part CMP-0075407-2, "Header, 100mil, 3x1, Gold, TH", Color=Black, Current_A=6.3A, Manufacturer=Samtec, Supplier Part Number 1=SAM1029-03-ND, Voltage_V=550V
J4 J6: library part CMP-0075403-1, "Header, 100mil, 1pos, Gold, TH", Color=Black, Current_A=6.3A, Manufacturer=Samtec, Supplier Part Number 1=SAM1029-01-ND, Voltage_V=550V
J5: library part CMP-0054903-1, "Header(shrouded), 2x1, R/A, TH", Manufacturer="TE Connectivity"
J7 J8: library part CMP-0055833-1, "SMA Straight Jack, Gold, 50 Ohm, TH", Manufacturer="Amphenol RF", Supplier Part Number 1=ARFX1231-ND
J9 J19 J20 J21: library part CMP-0075405-3, "Header, 100mil, 2x1, Gold, TH", Color=Black, Current_A=6.3A, Manufacturer=Samtec, Supplier Part Number 1=SAM1029-02-ND, Voltage_V=550V
J12: library part CMP-0085931-1, "Connector, 1 Port RJ45, Gold, R/A, TH", Manufacturer="Wurth Elektronik"
J16 J17: library part CMP-0054792-1, "Header, 2.54 mm, 1x1, Gold, TH", Manufacturer="Wurth Elektronik", Supplier Part Number 1=732-5314-ND
J18: library part CMP-0055301-1, "Connector, Receptacle, Micro-USB Type AB, R/A, Bottom Mount SMT", Manufacturer=Molex, Supplier Part Number 1=WM17143CT-ND
J22: library part CMP-0054778-4, "WR-DC DC Power Jack, R/A, TH", Color=Black, Manufacturer="Wurth Elektronik", Supplier Part Number 1=732-5930-ND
